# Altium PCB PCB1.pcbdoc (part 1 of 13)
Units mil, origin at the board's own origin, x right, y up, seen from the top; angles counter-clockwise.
Board outline 5895.51 x 5895.51 mil, 8 copper layers (Top Layer, L2_GND1, L3_SIG1, L4_GND2, L5_PWR, L6_SIG2, L7_GND3, Bottom Layer), stack 63.761 mil thick; 673 components, 558 nets, 2797 pads, 1861 vias.
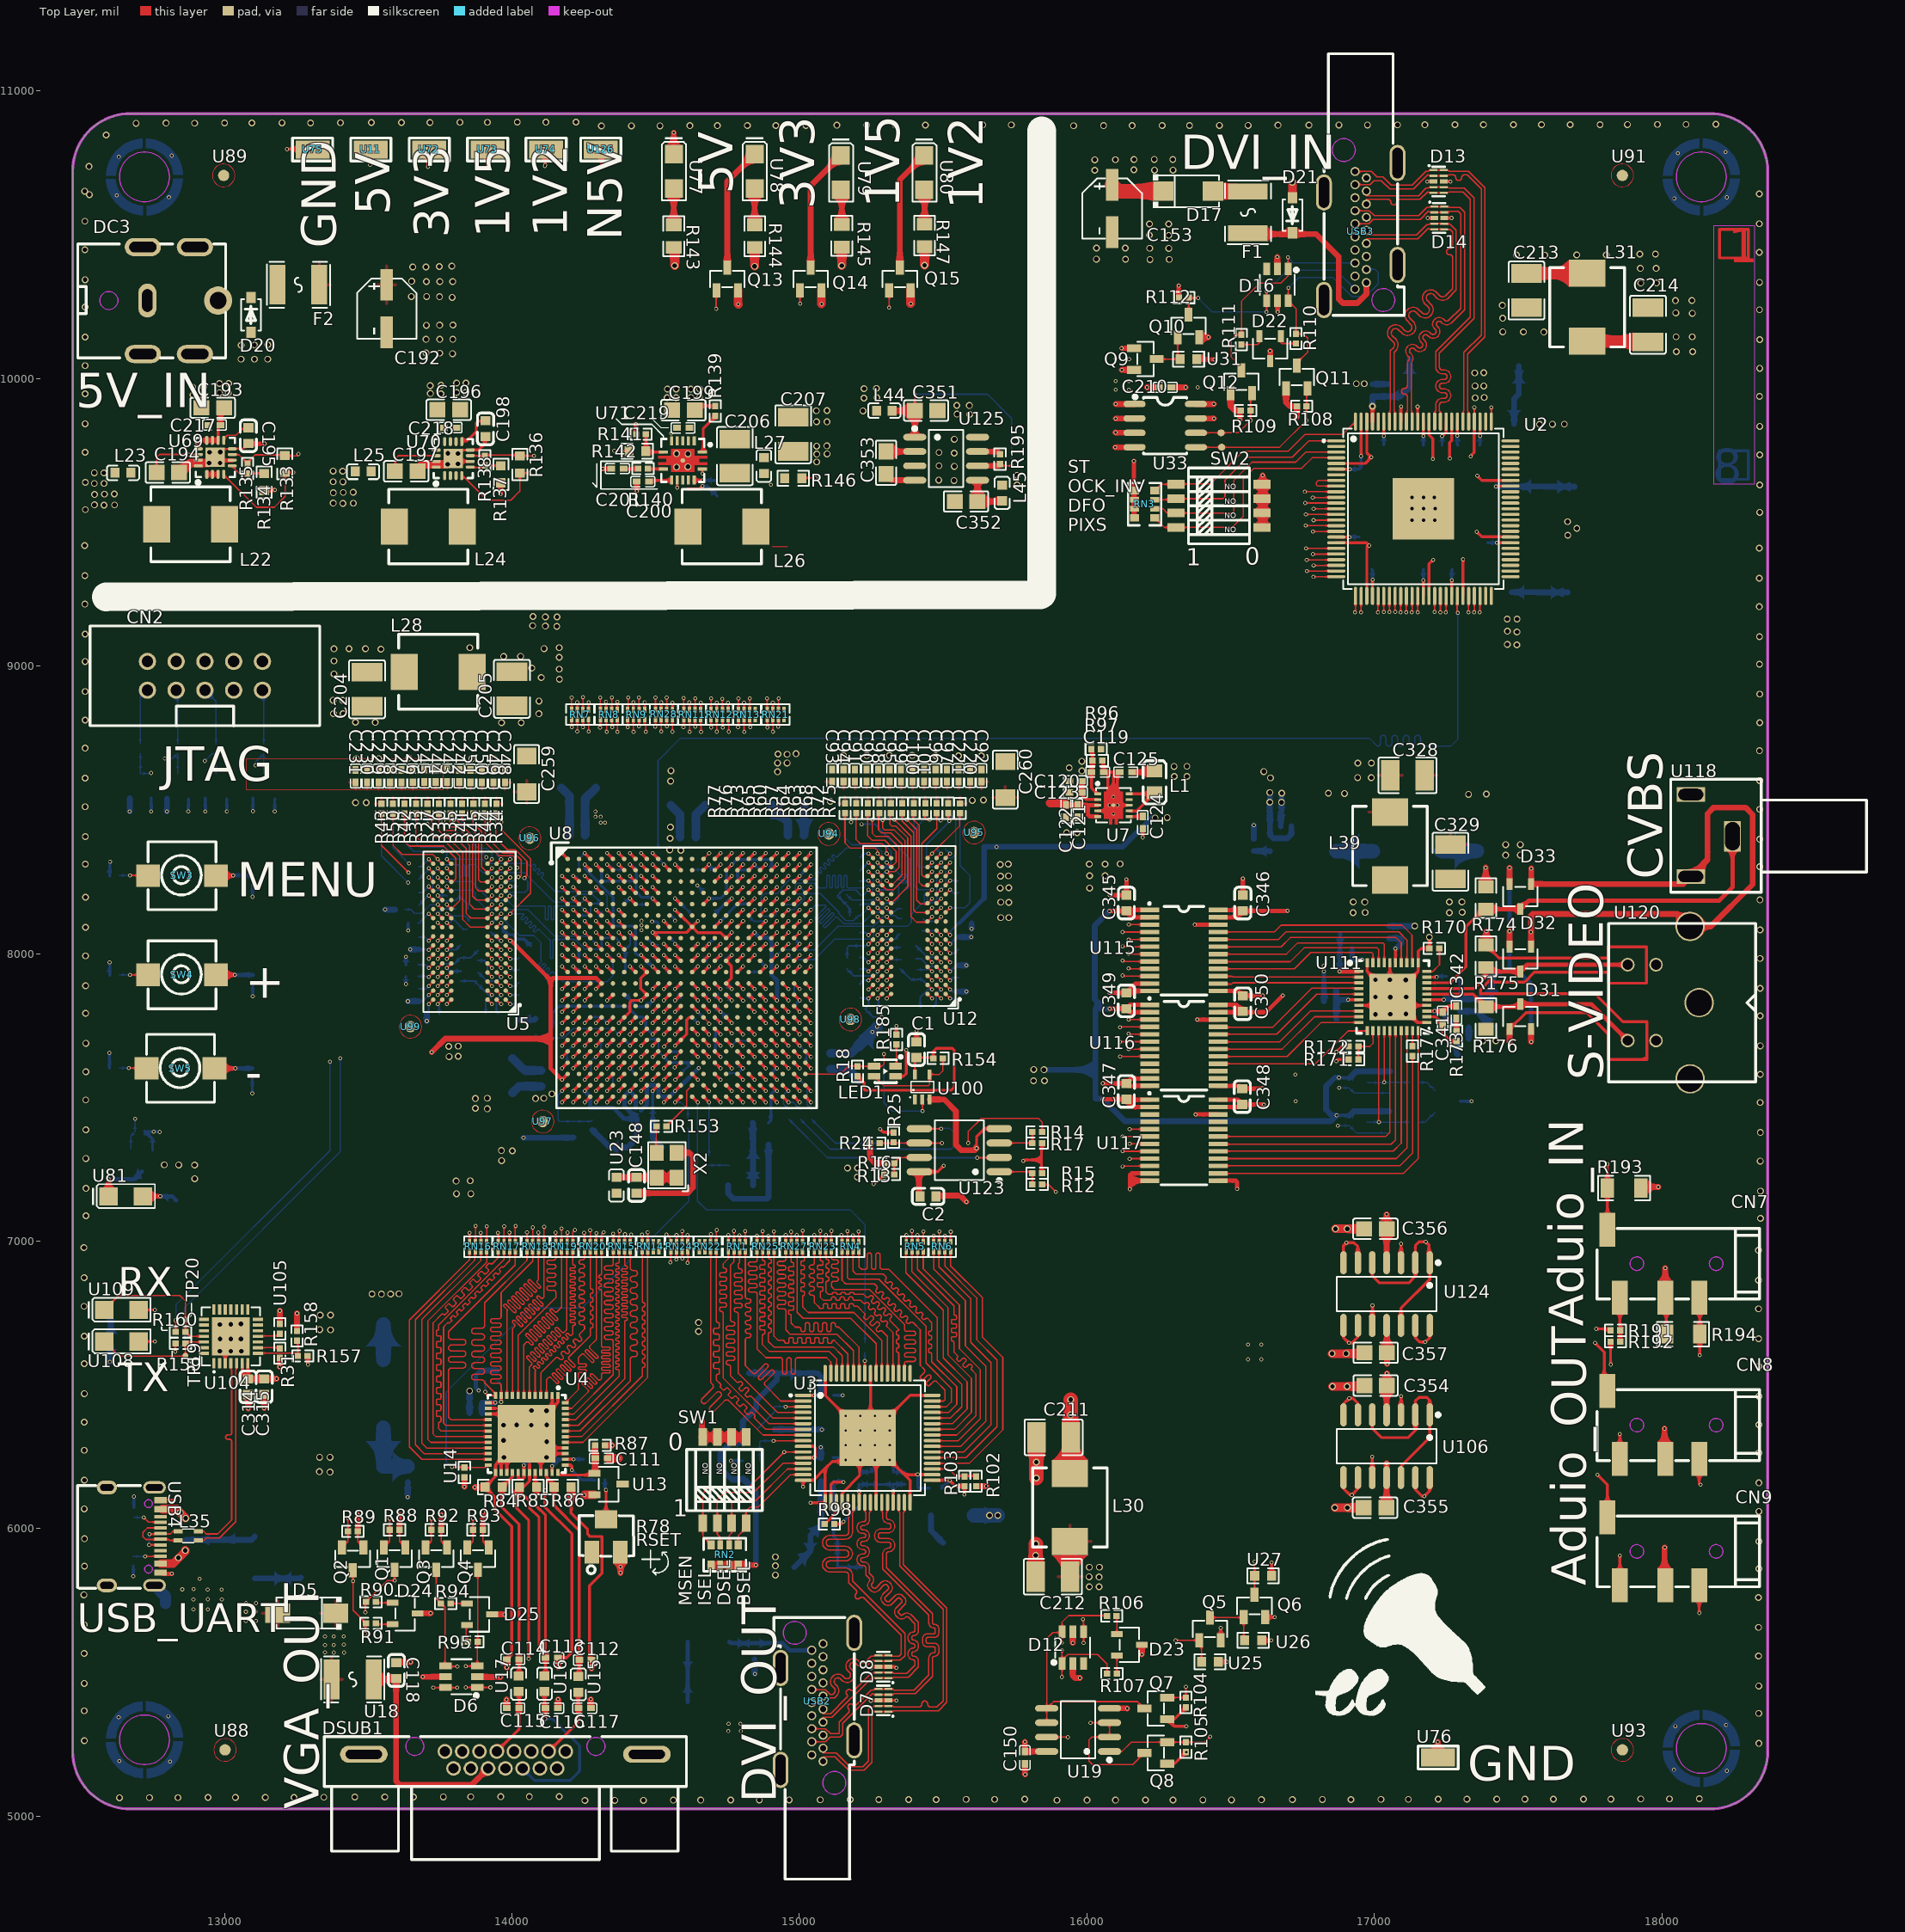
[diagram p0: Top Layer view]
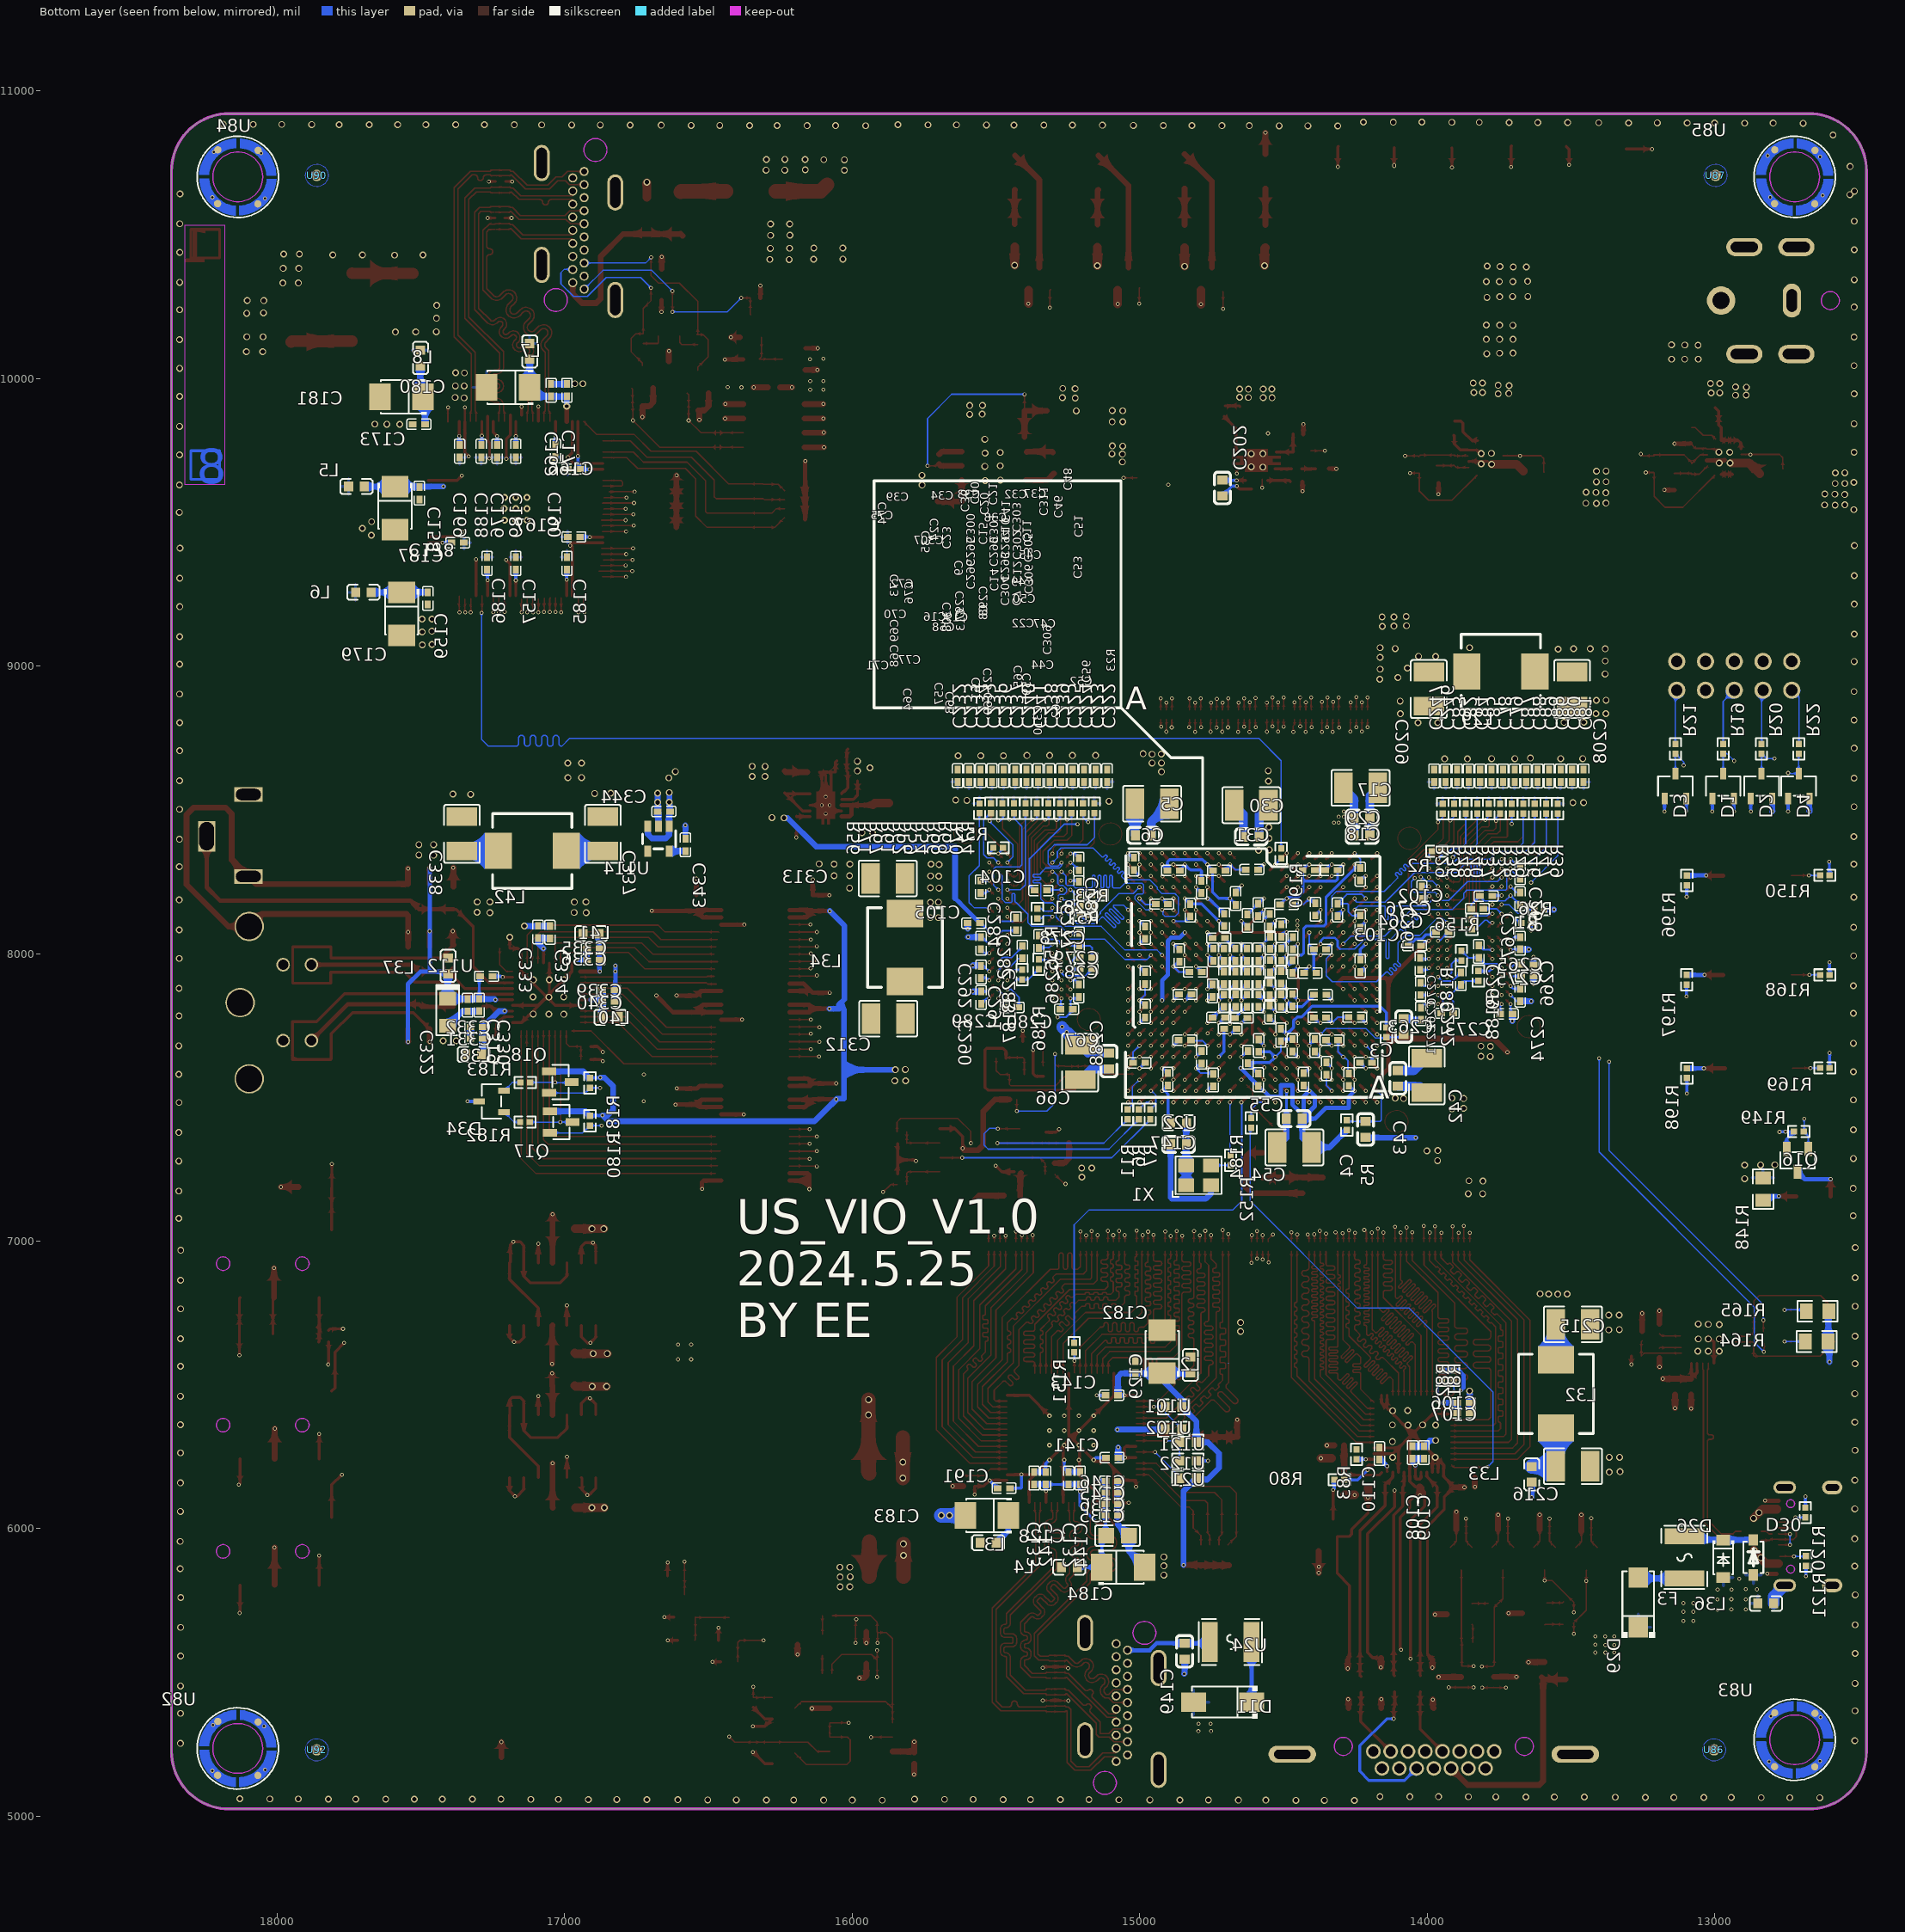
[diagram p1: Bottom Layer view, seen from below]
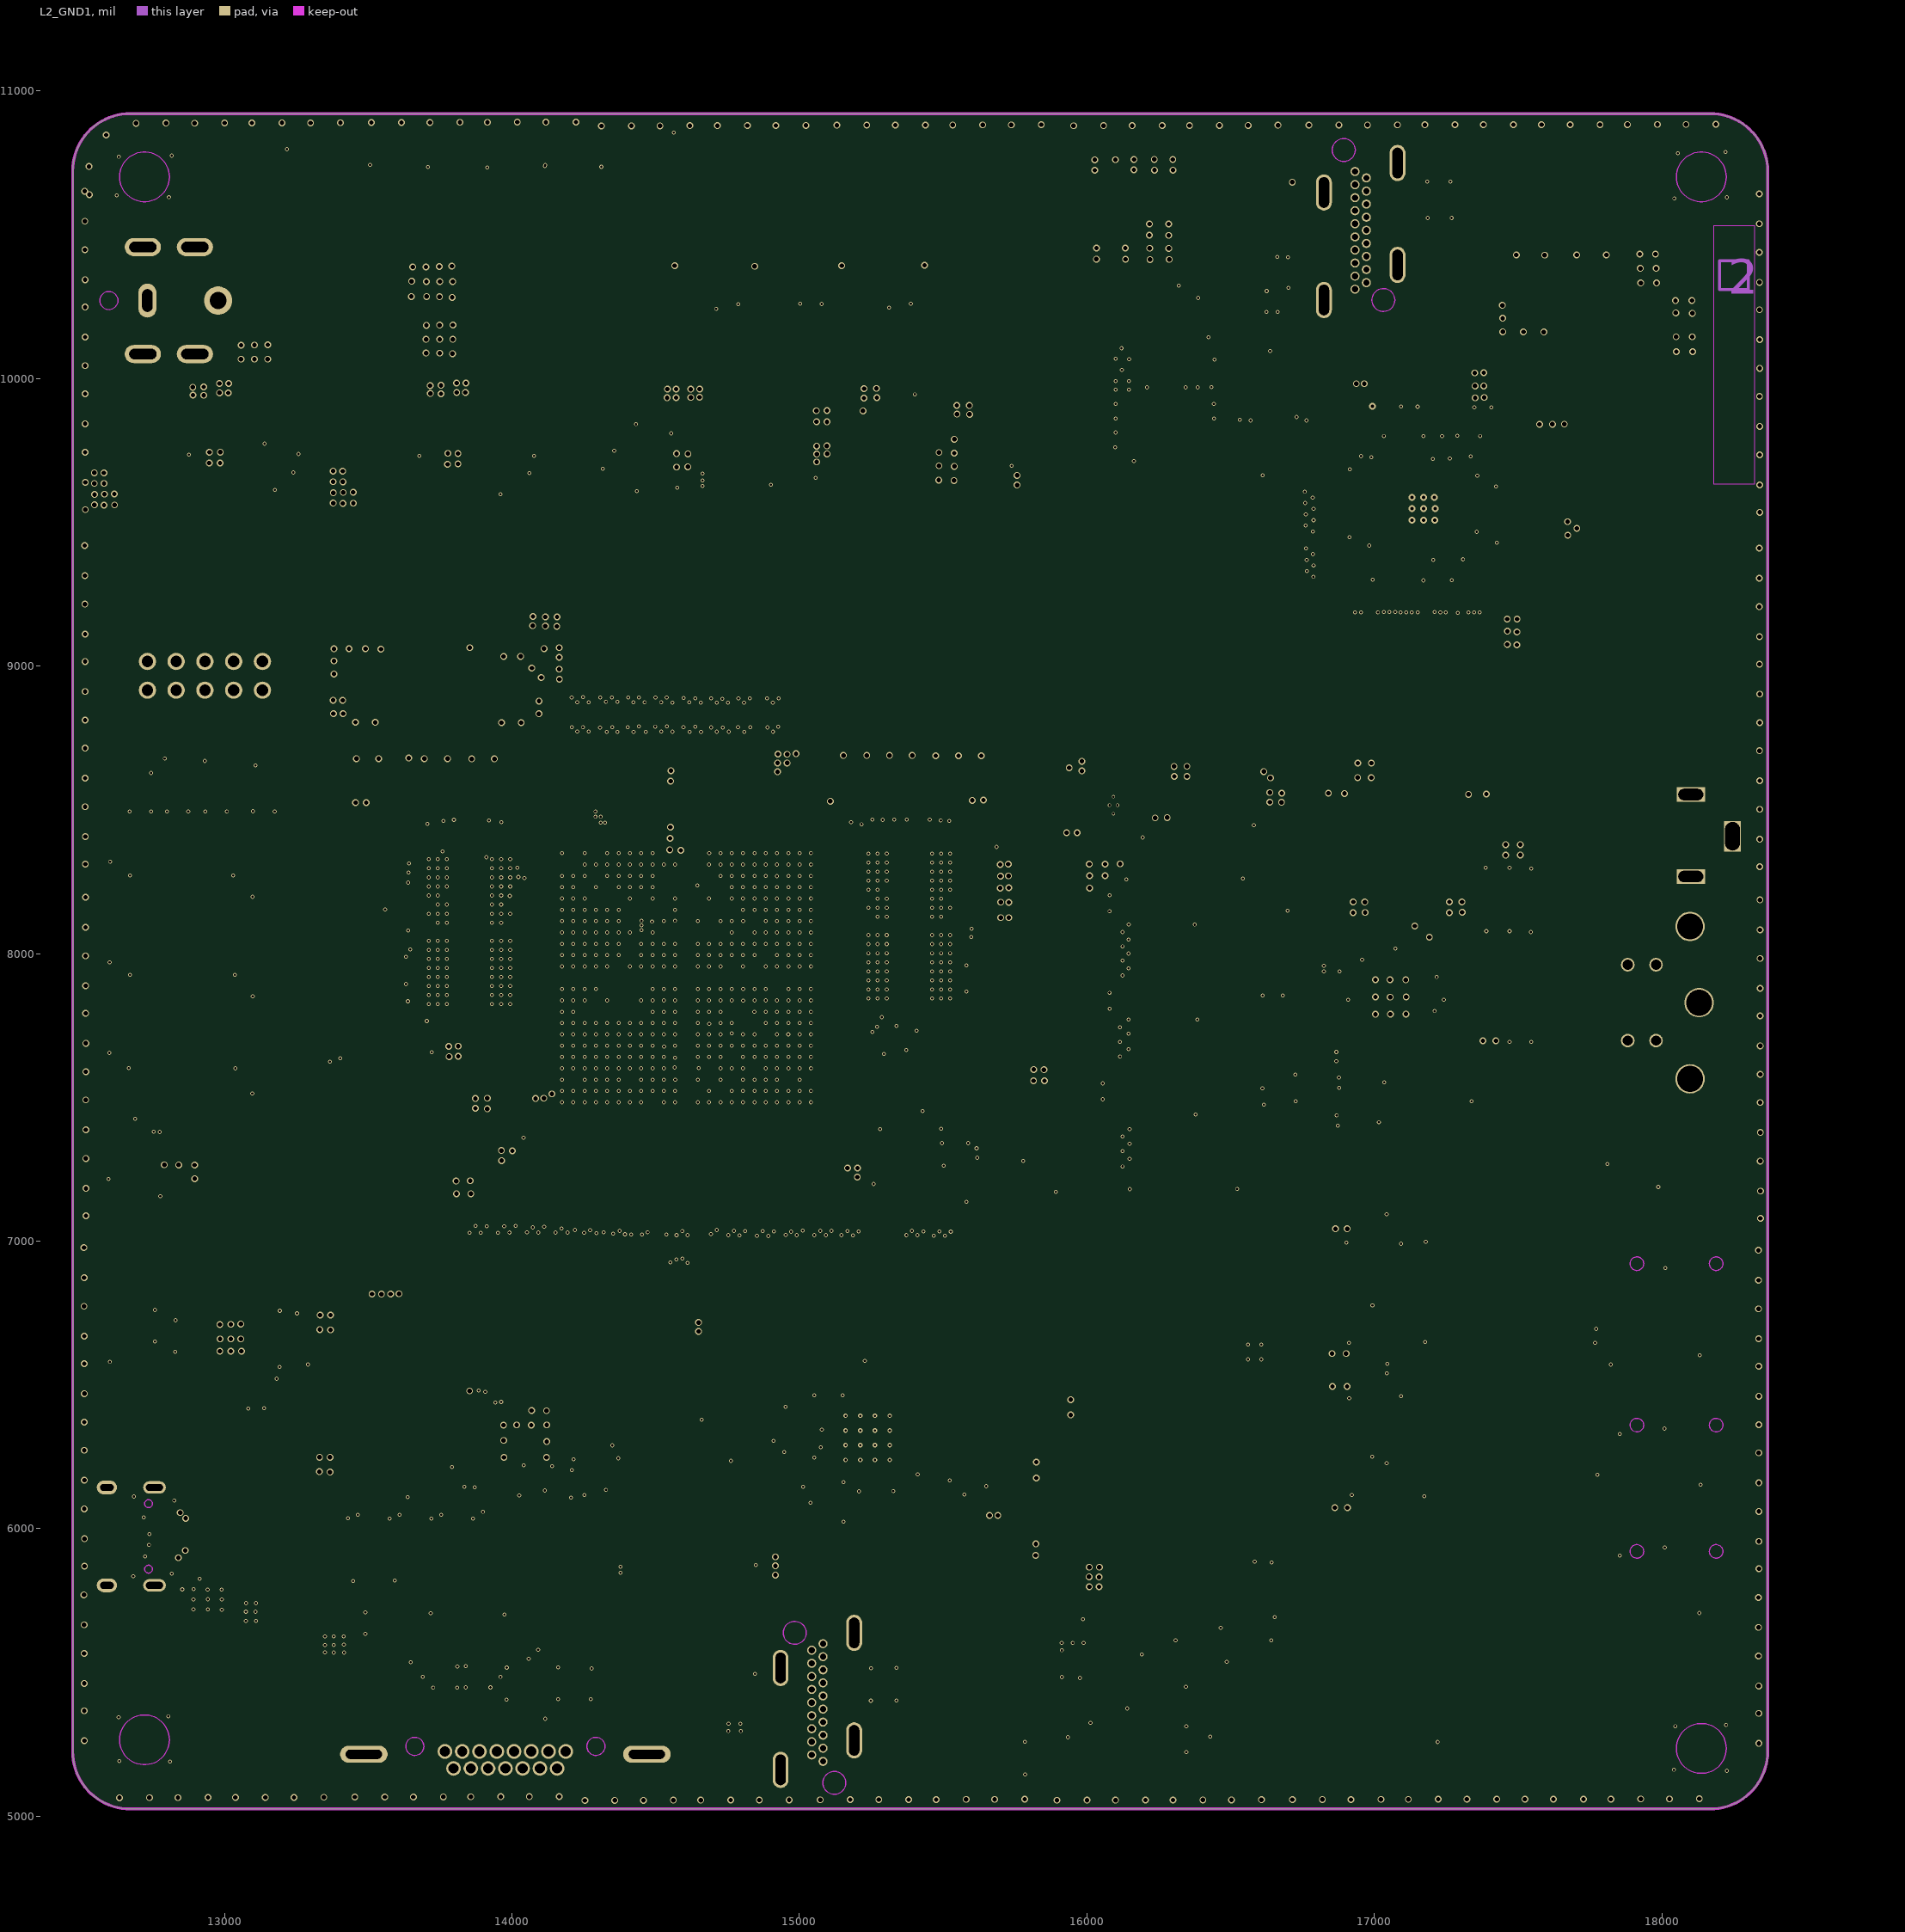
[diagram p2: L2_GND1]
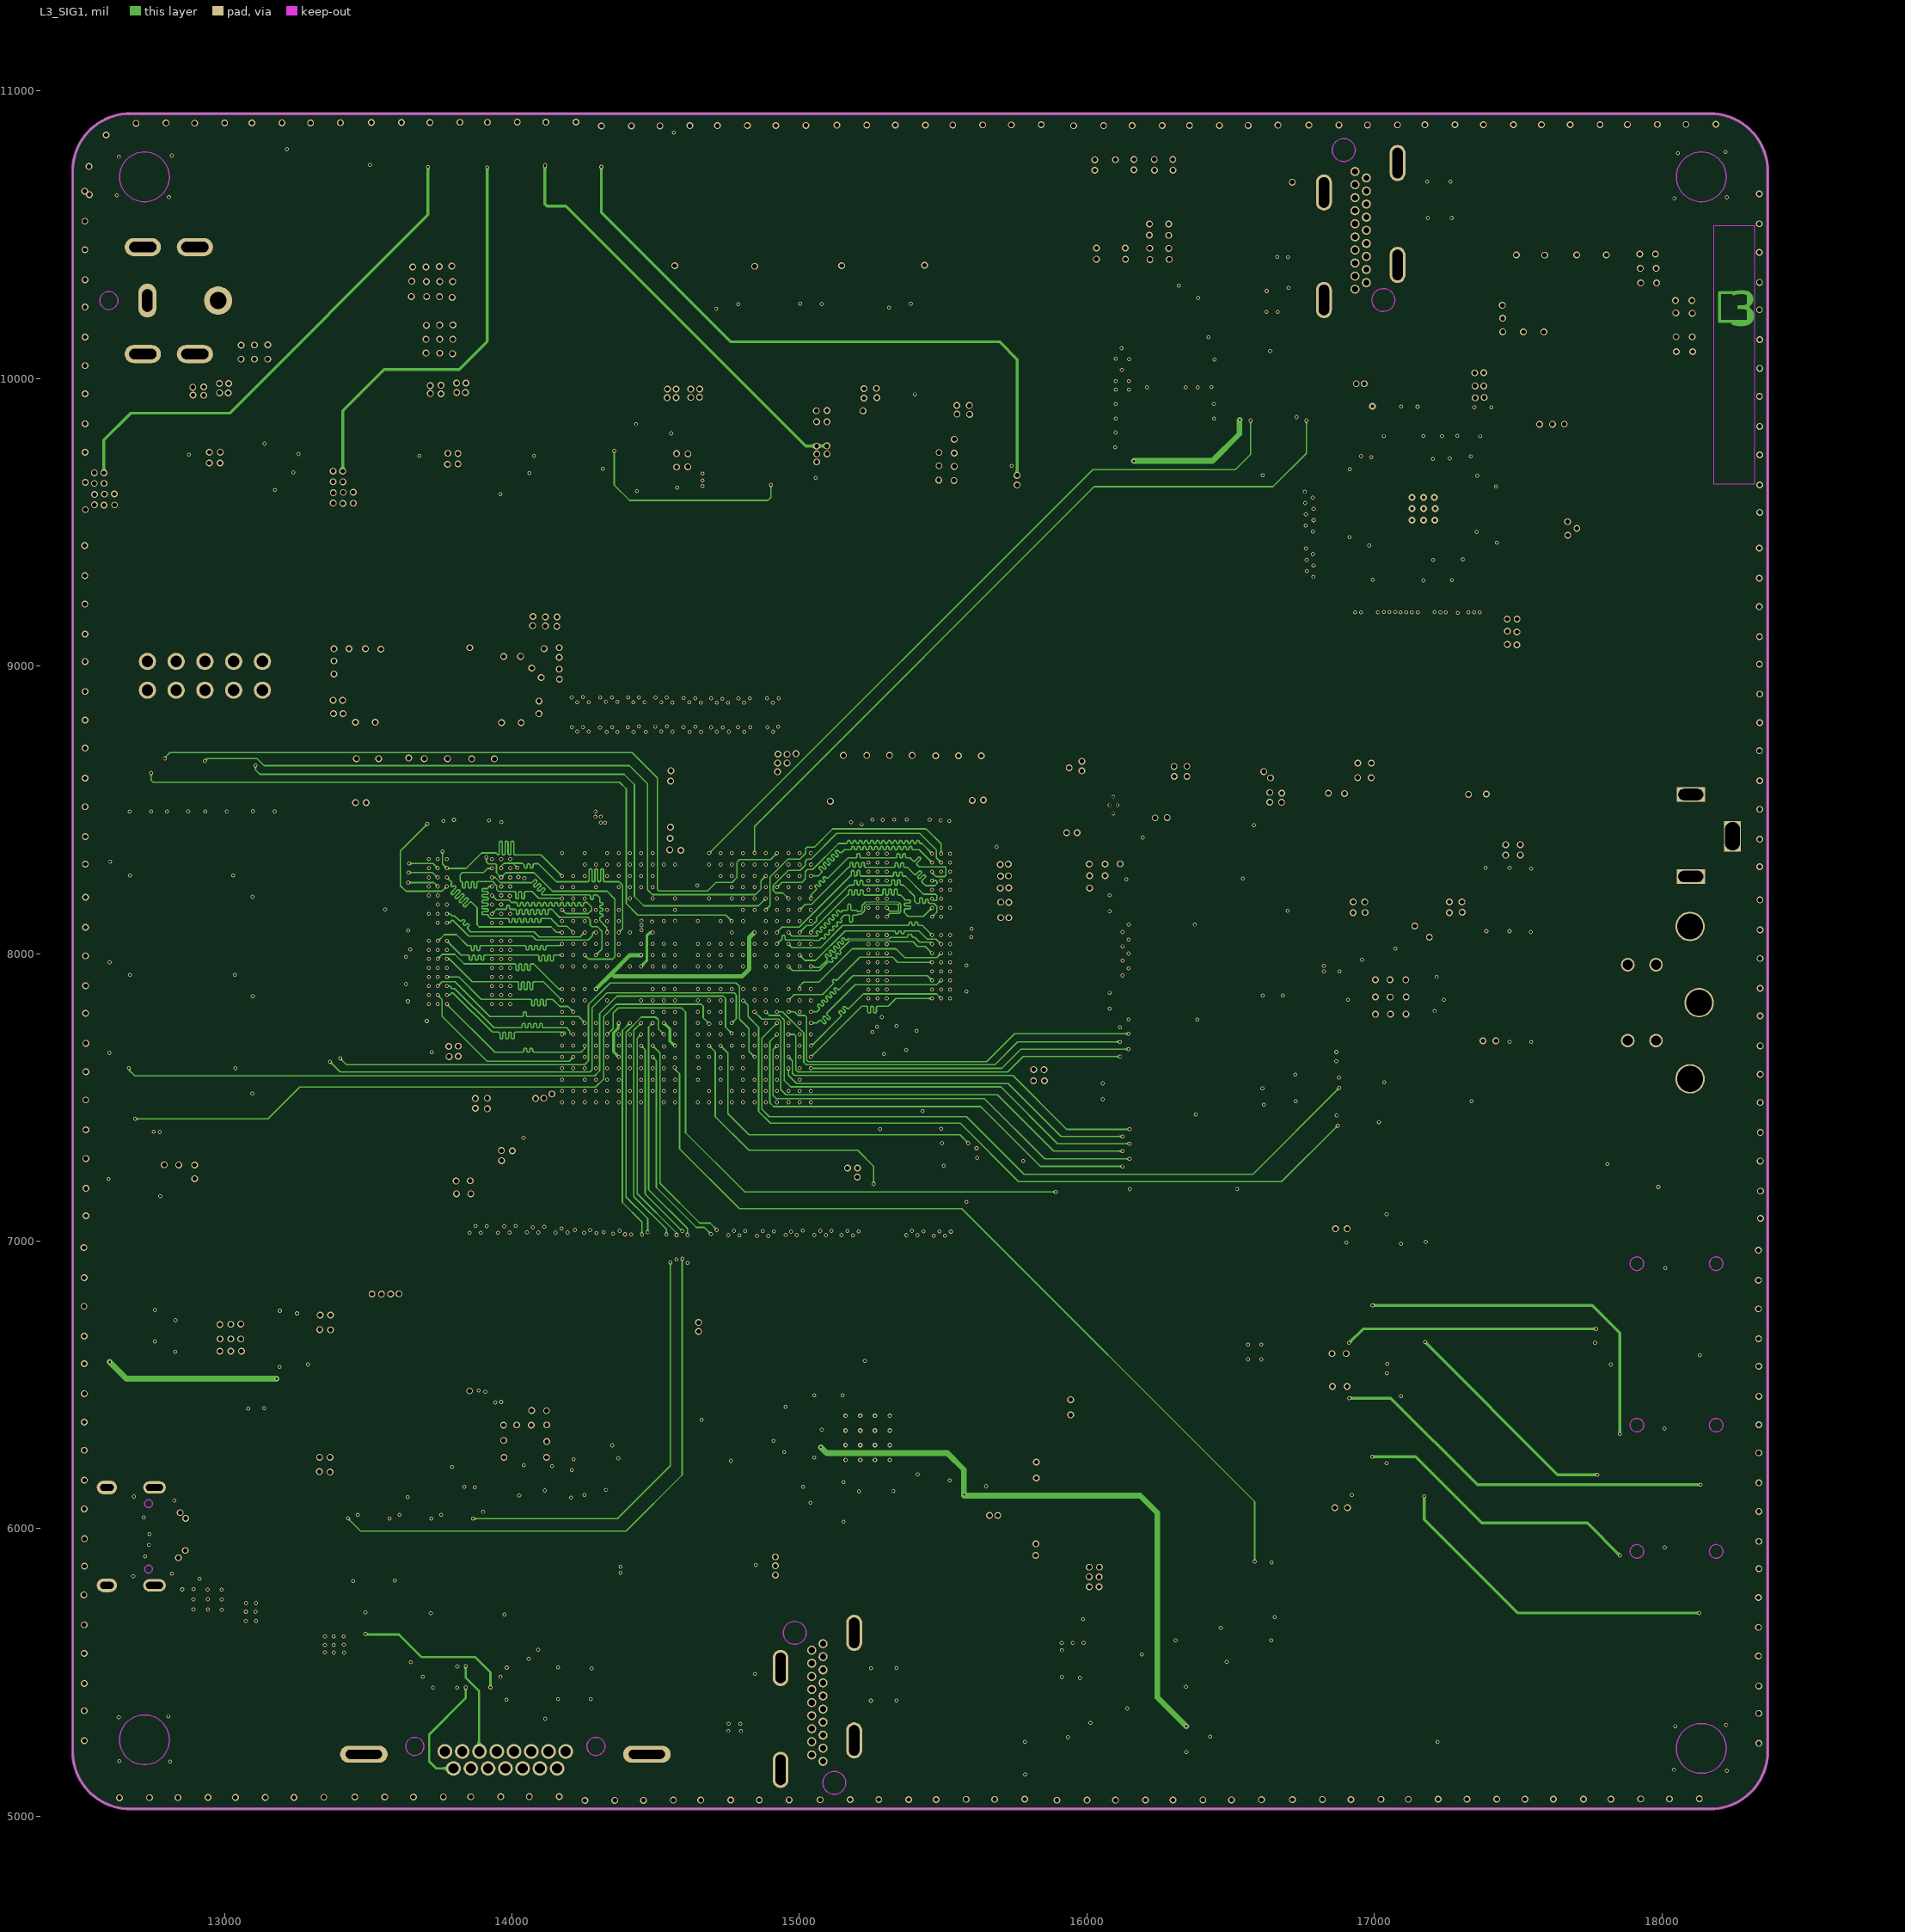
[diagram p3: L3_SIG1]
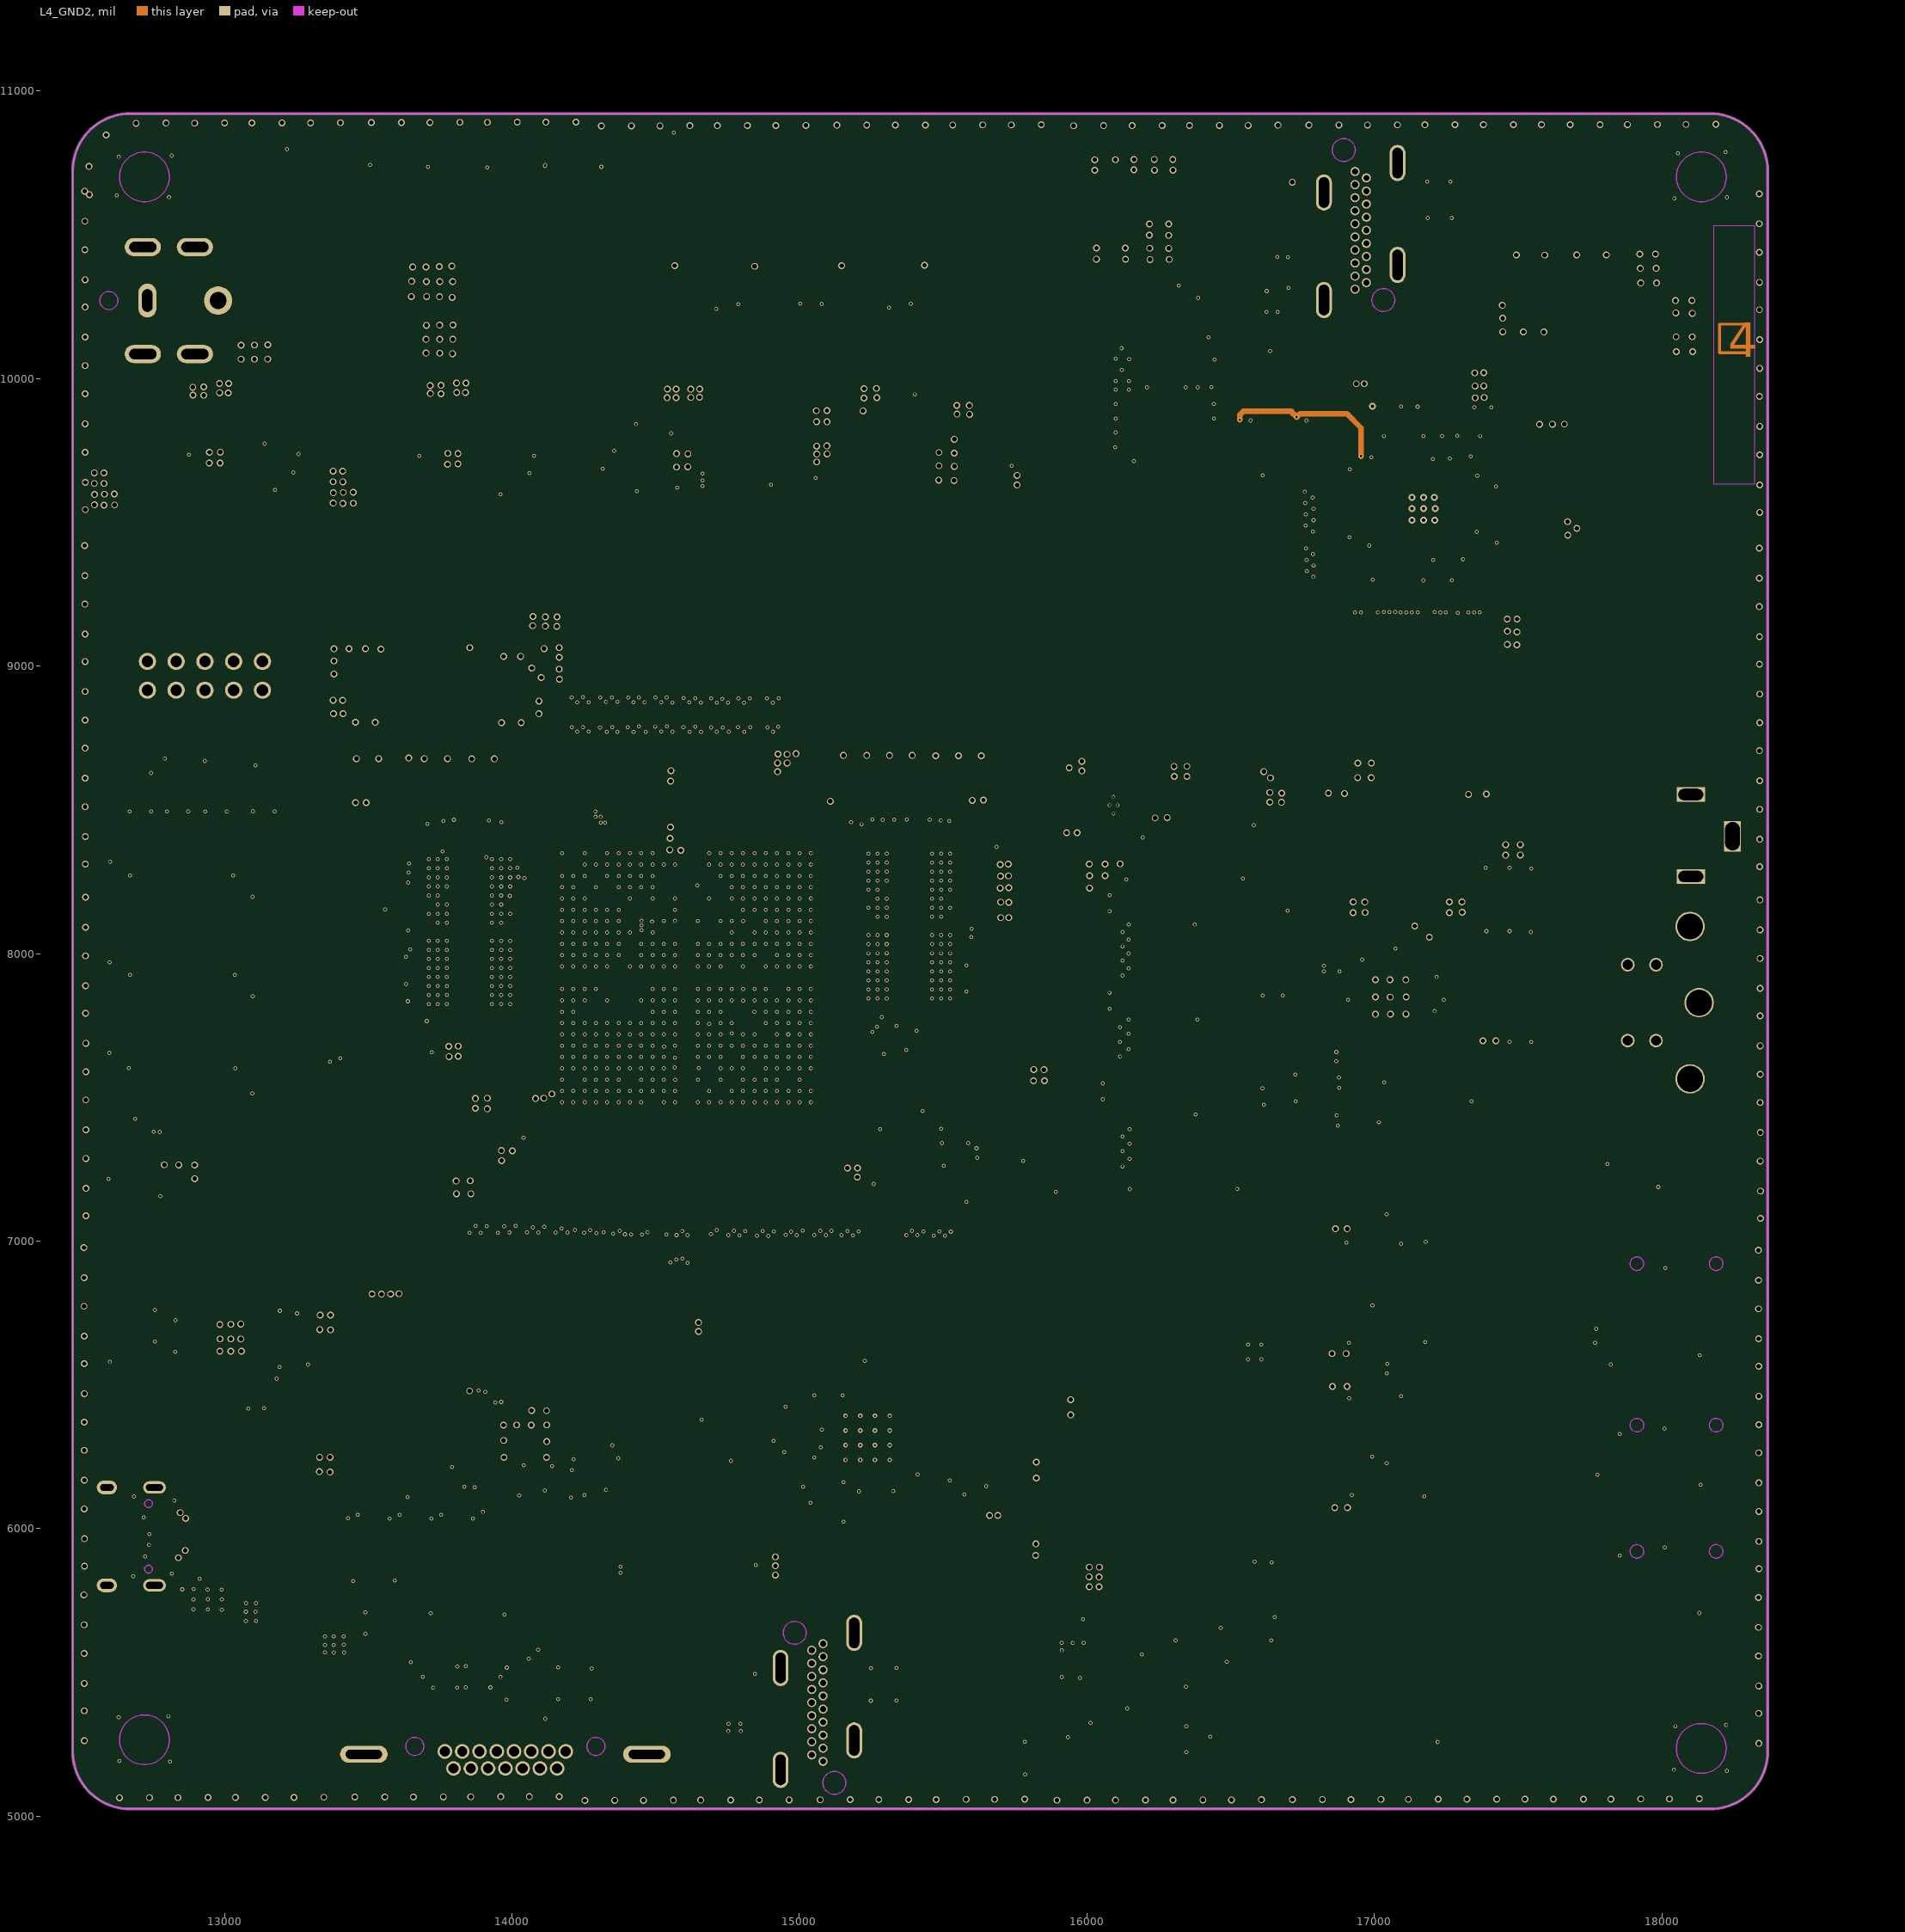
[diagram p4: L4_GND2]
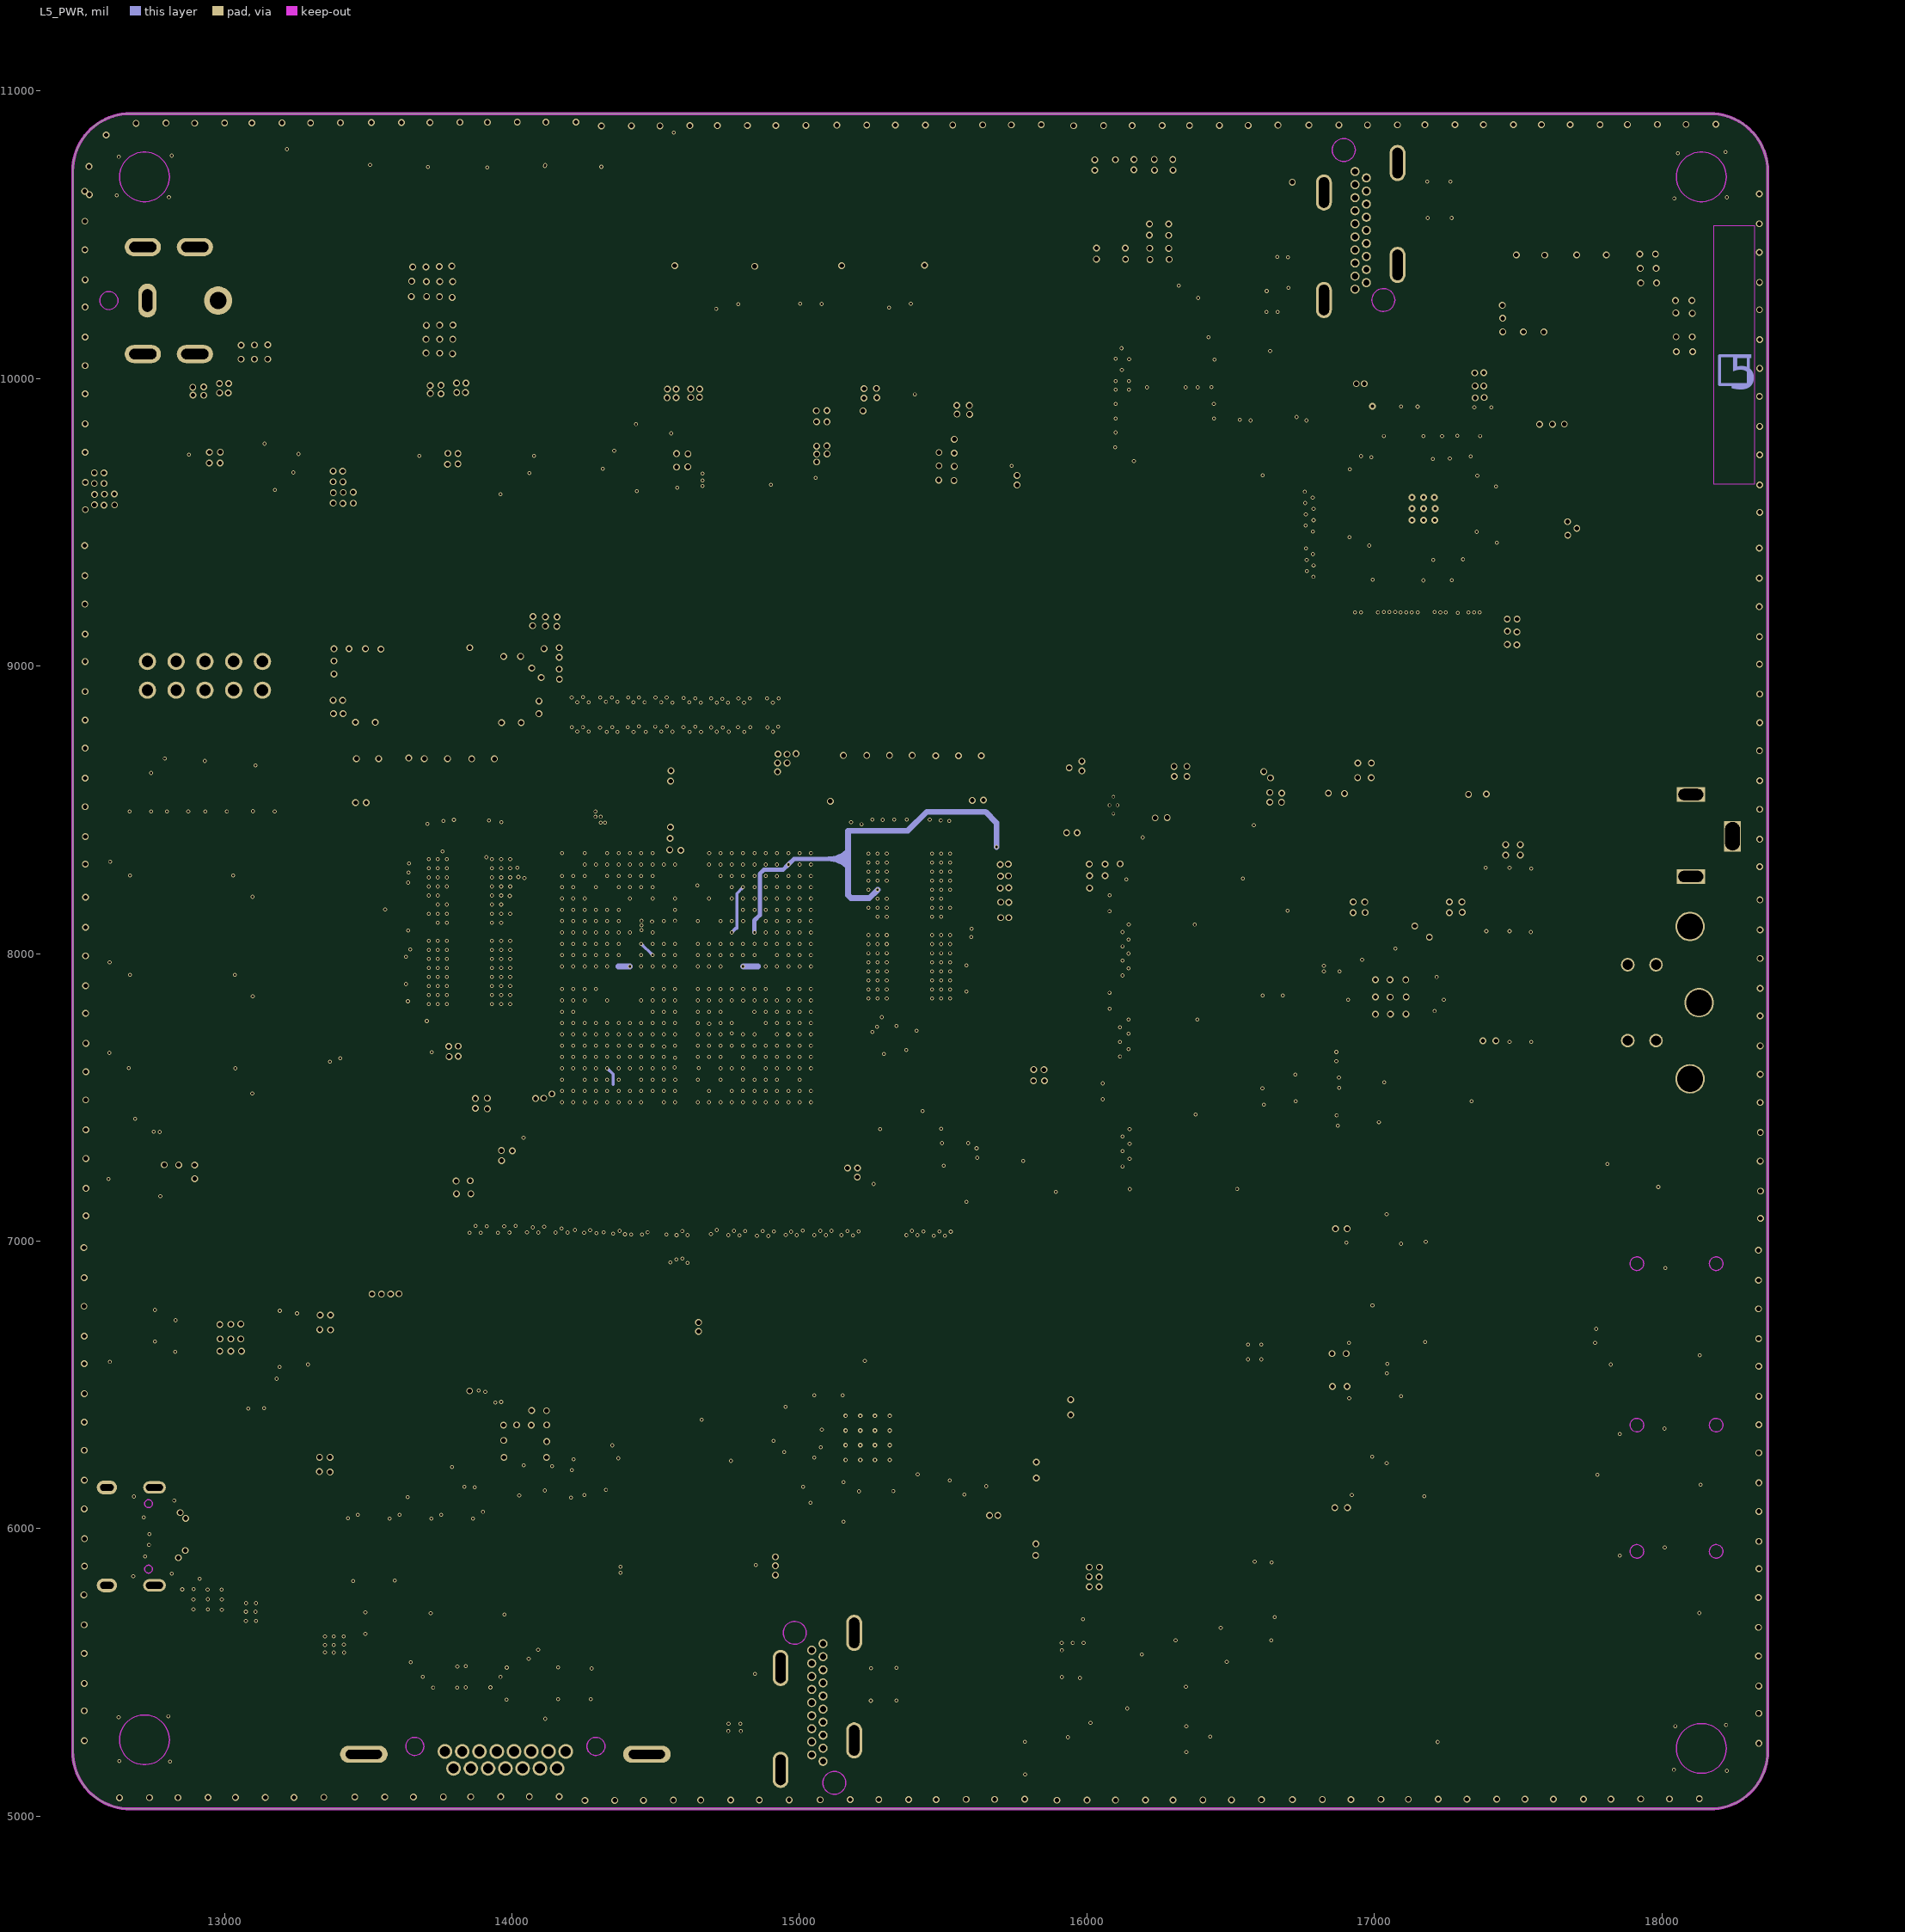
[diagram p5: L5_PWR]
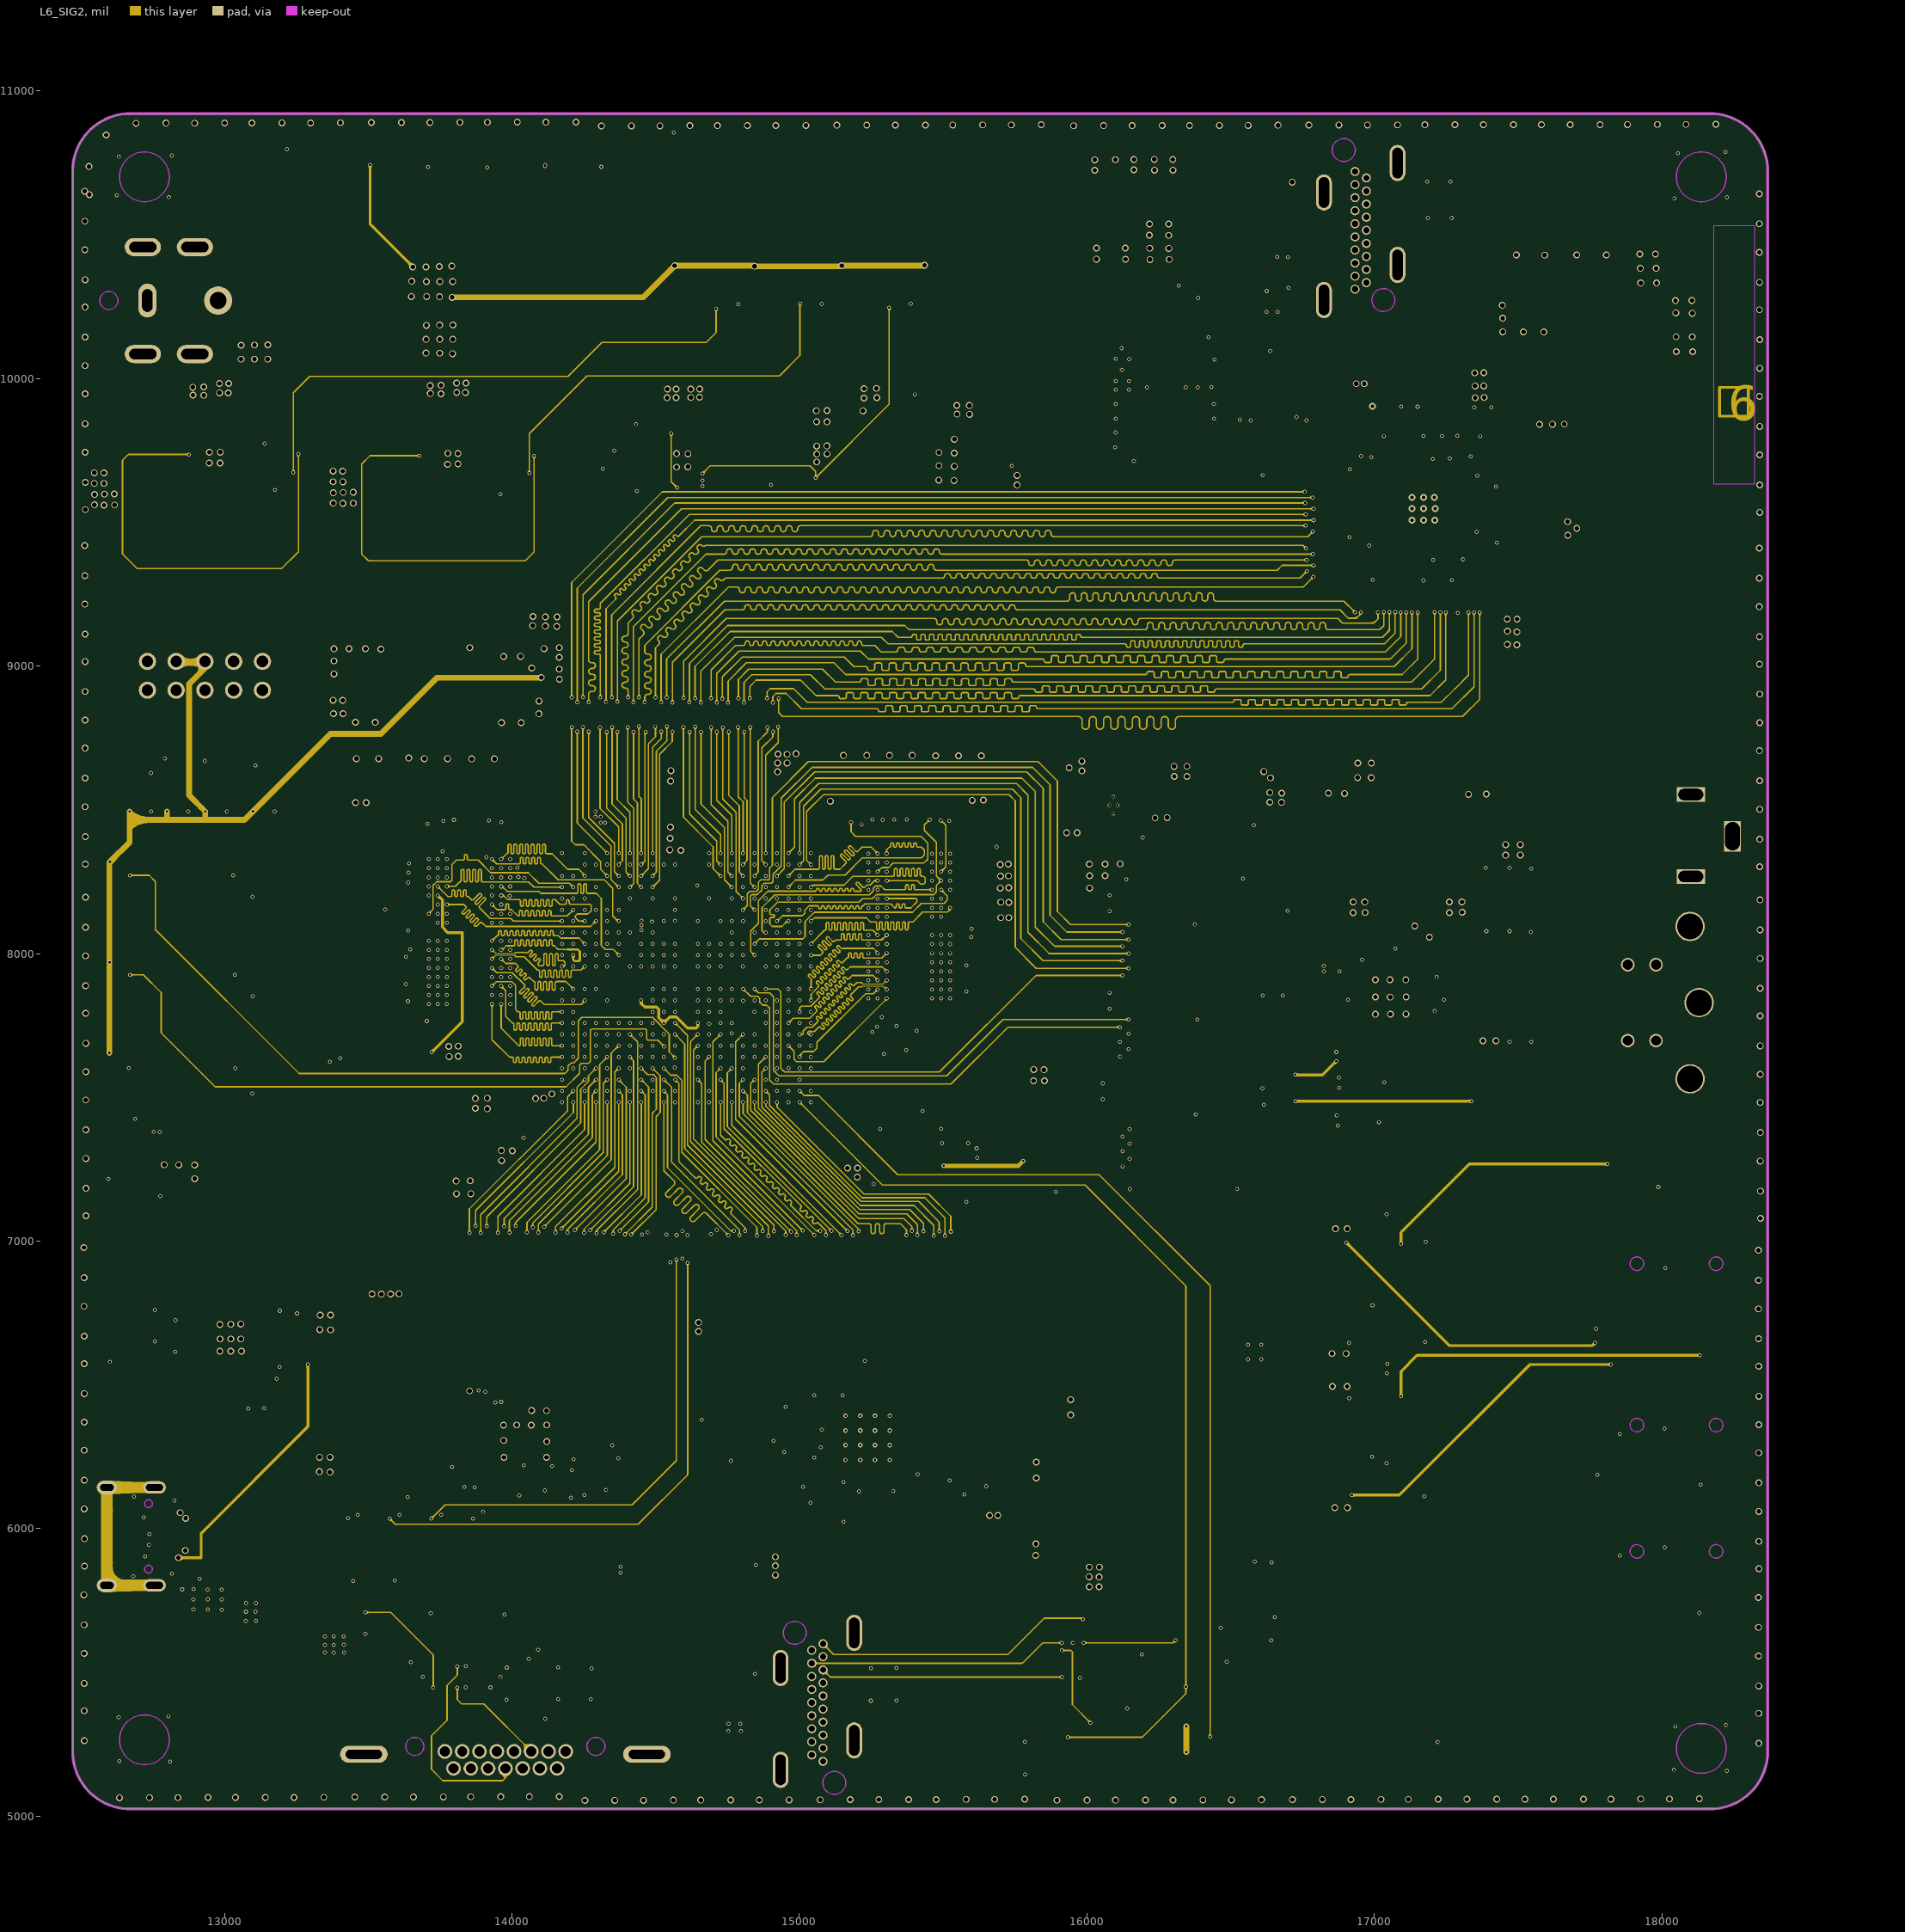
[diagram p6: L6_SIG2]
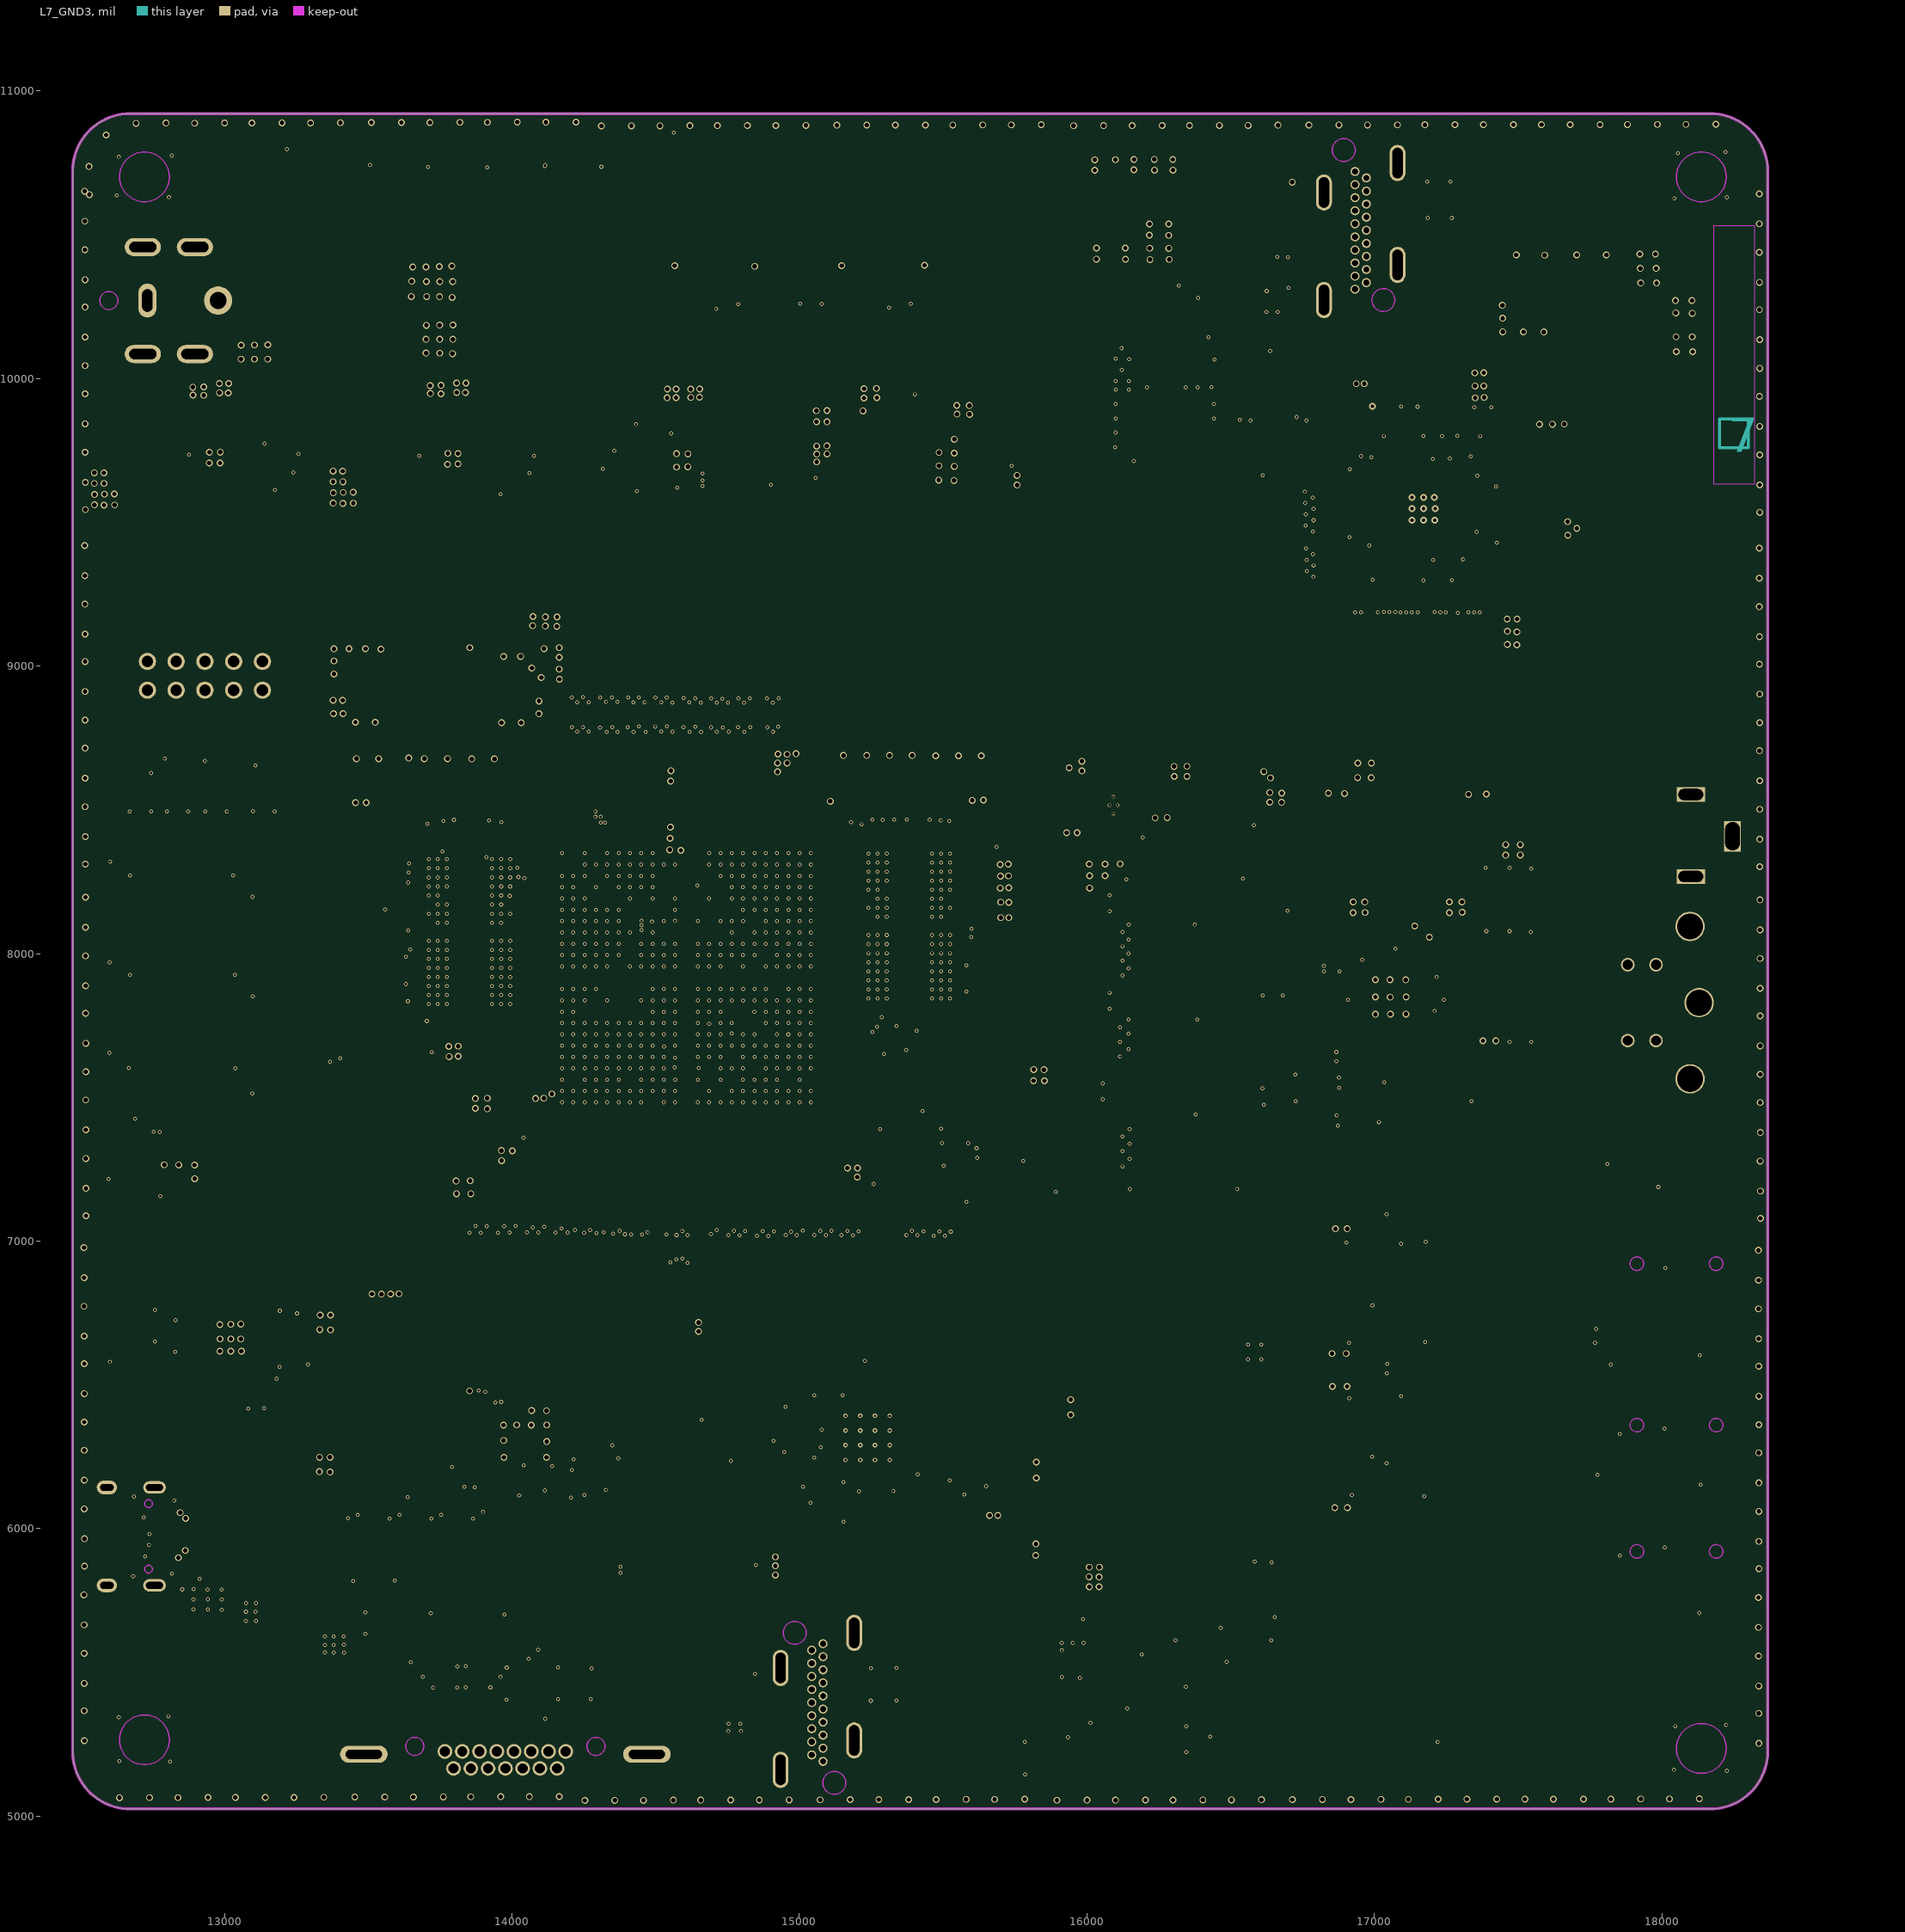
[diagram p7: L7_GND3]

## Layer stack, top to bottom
Top Layer: signal copper 1.378
Dielectric1: surface 3.008, 1080 RC67% 3.3mil, Dk 0
L2_GND1: signal copper 0.598
Dielectric2: surface 11.811, 0.3mm H/HOZ 不含铜, Dk 0
L3_SIG1: signal copper 0.598
Dielectric3: surface 7.984, 7628 RC49% 8.6mil, Dk 0
L4_GND2: signal copper 0.598
Dielectric4: surface 11.811, 0.3mm H/HOZ 不含铜, Dk 0
L5_PWR: signal copper 0.598
Dielectric5: surface 7.984, 7628 RC49% 8.6mil, Dk 0
L6_SIG2: signal copper 0.598
Dielectric6: surface 11.811, 0.3mm H/HOZ 不含铜, Dk 0
L7_GND3: signal copper 0.598
Dielectric7: surface 3.008, 1080 RC67% 3.3mil, Dk 0
Bottom Layer: signal copper 1.378

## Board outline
12672.36,10921 18167.87,10921 cw(c18167.87,10721) 18367.87,10721 18367.87,5225.49 cw(c18167.87,5225.49) 18167.87,5025.49 12672.36,5025.49 cw(c12672.36,5225.49) 12472.36,5225.49 12472.36,10721 cw(c12672.36,10721)

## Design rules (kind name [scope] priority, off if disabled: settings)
BoardOutlineClearance copperThickness1oz [All] p0: genericclearance=10 ignorepadtopadclearanceinfootprint=FALSE except(0: Arc-SplitContinuation Track-SplitContinuation SMDPad-SplitContinuation THPad-SplitContinuation Via-SplitContinuation Fill-SplitContinuation Poly-SplitContinuation Region-SplitContinuation Text-SplitContinuation)
BoardOutlineClearance copperThickness2oz [All] p0: genericclearance=10 ignorepadtopadclearanceinfootprint=FALSE except(0: Arc-SplitContinuation Track-SplitContinuation SMDPad-SplitContinuation THPad-SplitContinuation Via-SplitContinuation Fill-SplitContinuation Poly-SplitContinuation Region-SplitContinuation Text-SplitContinuation)
BoardOutlineClearance copperThicknessInner0.5oz [All] p0: genericclearance=10 ignorepadtopadclearanceinfootprint=FALSE except(0: Arc-SplitContinuation Track-SplitContinuation SMDPad-SplitContinuation THPad-SplitContinuation Via-SplitContinuation Fill-SplitContinuation Poly-SplitContinuation Region-SplitContinuation Text-SplitContinuation)
BoardOutlineClearance BGA [All] p0: genericclearance=10 ignorepadtopadclearanceinfootprint=FALSE except(0: Arc-SplitContinuation Track-SplitContinuation SMDPad-SplitContinuation THPad-SplitContinuation Via-SplitContinuation Fill-SplitContinuation Poly-SplitContinuation Region-SplitContinuation Text-SplitContinuation)
BoardOutlineClearance Plane_innerPlane [All] p0: genericclearance=10 ignorepadtopadclearanceinfootprint=FALSE except(0: Arc-SplitContinuation Track-SplitContinuation SMDPad-SplitContinuation THPad-SplitContinuation Via-SplitContinuation Fill-SplitContinuation Poly-SplitContinuation Region-SplitContinuation Text-SplitContinuation)
BoardOutlineClearance Copper_copperRegion1 [All] p0: genericclearance=10 ignorepadtopadclearanceinfootprint=FALSE except(0: Arc-SplitContinuation Track-SplitContinuation SMDPad-SplitContinuation THPad-SplitContinuation Via-SplitContinuation Fill-SplitContinuation Poly-SplitContinuation Region-SplitContinuation Text-SplitContinuation)
BoardOutlineClearance Copper_copperRegion2 [All] p0: genericclearance=10 ignorepadtopadclearanceinfootprint=FALSE except(0: Arc-SplitContinuation Track-SplitContinuation SMDPad-SplitContinuation THPad-SplitContinuation Via-SplitContinuation Fill-SplitContinuation Poly-SplitContinuation Region-SplitContinuation Text-SplitContinuation)
BoardOutlineClearance Copper_copperRegion3 [All] p0: genericclearance=10 ignorepadtopadclearanceinfootprint=FALSE except(0: Arc-SplitContinuation Track-SplitContinuation SMDPad-SplitContinuation THPad-SplitContinuation Via-SplitContinuation Fill-SplitContinuation Poly-SplitContinuation Region-SplitContinuation Text-SplitContinuation)
BoardOutlineClearance otherClearance [All] p0: genericclearance=10 ignorepadtopadclearanceinfootprint=FALSE except(0: Arc-SplitContinuation Track-SplitContinuation SMDPad-SplitContinuation THPad-SplitContinuation Via-SplitContinuation Fill-SplitContinuation Poly-SplitContinuation Region-SplitContinuation Text-SplitContinuation)
Clearance copperThickness1oz [All] p1: gap=7 ignorepadtopadclearanceinfootprint=FALSE
Clearance copperThickness2oz [All] p1: gap=7 ignorepadtopadclearanceinfootprint=FALSE
Clearance copperThicknessInner0.5oz [All] p1: gap=7 ignorepadtopadclearanceinfootprint=FALSE
Clearance BGA [All] p1: gap=7 ignorepadtopadclearanceinfootprint=FALSE
Clearance Plane_innerPlane [All] p1: gap=7 ignorepadtopadclearanceinfootprint=FALSE
Clearance Copper_copperRegion1 [All] p1: gap=7 ignorepadtopadclearanceinfootprint=FALSE
Clearance Copper_copperRegion2 [All] p1: gap=7 ignorepadtopadclearanceinfootprint=FALSE
Clearance Copper_copperRegion3 [All] p1: gap=7 ignorepadtopadclearanceinfootprint=FALSE
Clearance otherClearance [All] p1: gap=7 ignorepadtopadclearanceinfootprint=FALSE
DiffPairsRouting differentialPair [All] p1: maxuncoupledlength=10 minlimit=6 maxlimit=Infinity mostfreqgap=9 toplayer_minwidth=4 toplayer_prefwidth=10 toplayer_maxwidth=100 bottomlayer_minwidth=4 bottomlayer_prefwidth=10 bottomlayer_maxwidth=100 midlayer1_minwidth=4 midlayer1_prefwidth=10 midlayer1_maxwidth=100 midlayer2_minwidth=4 midlayer2_prefwidth=10 midlayer2_maxwidth=100 midlayer3_minwidth=4 midlayer3_prefwidth=10 midlayer3_maxwidth=100 midlayer4_minwidth=4 midlayer4_prefwidth=10 midlayer4_maxwidth=100 midlayer5_minwidth=4 midlayer5_prefwidth=10 midlayer5_maxwidth=100 midlayer6_minwidth=4 midlayer6_prefwidth=10 midlayer6_maxwidth=100
DiffPairsRouting 100R_L1/8 [All] p1: maxuncoupledlength=10 minlimit=3.5 maxlimit=Infinity mostfreqgap=9 toplayer_minwidth=3.5 toplayer_prefwidth=4 toplayer_maxwidth=10 bottomlayer_minwidth=3.5 bottomlayer_prefwidth=4 bottomlayer_maxwidth=10 midlayer1_minwidth=3.5 midlayer1_prefwidth=4 midlayer1_maxwidth=10 midlayer2_minwidth=3.5 midlayer2_prefwidth=4 midlayer2_maxwidth=10 midlayer3_minwidth=3.5 midlayer3_prefwidth=4 midlayer3_maxwidth=10 midlayer4_minwidth=3.5 midlayer4_prefwidth=4 midlayer4_maxwidth=10 midlayer5_minwidth=3.5 midlayer5_prefwidth=4 midlayer5_maxwidth=10 midlayer6_minwidth=3.5 midlayer6_prefwidth=4 midlayer6_maxwidth=10
DiffPairsRouting 100R_L3/6 [All] p1: maxuncoupledlength=10 minlimit=3.5 maxlimit=Infinity mostfreqgap=9 toplayer_minwidth=3.5 toplayer_prefwidth=6.2 toplayer_maxwidth=8 bottomlayer_minwidth=3.5 bottomlayer_prefwidth=6.2 bottomlayer_maxwidth=8 midlayer1_minwidth=3.5 midlayer1_prefwidth=6.2 midlayer1_maxwidth=8 midlayer2_minwidth=3.5 midlayer2_prefwidth=6.2 midlayer2_maxwidth=8 midlayer3_minwidth=3.5 midlayer3_prefwidth=6.2 midlayer3_maxwidth=8 midlayer4_minwidth=3.5 midlayer4_prefwidth=6.2 midlayer4_maxwidth=8 midlayer5_minwidth=3.5 midlayer5_prefwidth=6.2 midlayer5_maxwidth=8 midlayer6_minwidth=3.5 midlayer6_prefwidth=6.2 midlayer6_maxwidth=8
DiffPairsRouting 90R_L1/L8 [All] p1: maxuncoupledlength=10 minlimit=6 maxlimit=Infinity mostfreqgap=9 toplayer_minwidth=4 toplayer_prefwidth=5.1 toplayer_maxwidth=8 bottomlayer_minwidth=4 bottomlayer_prefwidth=5.1 bottomlayer_maxwidth=8 midlayer1_minwidth=4 midlayer1_prefwidth=5.1 midlayer1_maxwidth=8 midlayer2_minwidth=4 midlayer2_prefwidth=5.1 midlayer2_maxwidth=8 midlayer3_minwidth=4 midlayer3_prefwidth=5.1 midlayer3_maxwidth=8 midlayer4_minwidth=4 midlayer4_prefwidth=5.1 midlayer4_maxwidth=8 midlayer5_minwidth=4 midlayer5_prefwidth=5.1 midlayer5_maxwidth=8 midlayer6_minwidth=4 midlayer6_prefwidth=5.1 midlayer6_maxwidth=8
PasteMaskExpansion pasteMaskExpansion [All] p1: expansion=0
PlaneConnect innerPlane [All] p1: planeconnectstyle=Relief reliefexpansion=20 reliefentries=4 reliefconductorwidth=10 reliefairgap=10
PolygonConnect copperRegion1 [All] p1: connectstyle=Direct reliefentries=4 reliefconductorwidth=10 polygonreliefangle="90 Angle" airgapwidth=10
PolygonConnect copperRegion2 [All] p1: connectstyle=Direct reliefentries=4 reliefconductorwidth=10 polygonreliefangle="90 Angle" airgapwidth=10
PolygonConnect copperRegion3 [All] p1: connectstyle=Direct reliefentries=4 reliefconductorwidth=10 polygonreliefangle="90 Angle" airgapwidth=10
RoutingVias viaSize [All] p1: viastyle="Through Hole" holewidth=11.8 minholewidth=7.9 maxholewidth=248 width=11.8 minwidth=7.9 maxwidth=248
SolderMaskExpansion solderMaskExpansion [All] p1: useseparateexpansions=TRUE expansion=2 expansionbottom=2
Width copperThickness1oz [All] p1: maxlimit=100 minlimit=4 preferedwidth=10
Width copperThickness2oz [All] p1: maxlimit=100 minlimit=8 preferedwidth=10
Width copperThickness0.5oz [All] p1: maxlimit=100 minlimit=4 preferedwidth=10
Width 50R_L1/L8 [All] p1: maxlimit=50 minlimit=4 preferedwidth=5
Width 50R_L3/6 [All] p1: maxlimit=50 minlimit=4 preferedwidth=8
Width 45R_L1/L8 [All] p1: maxlimit=50 minlimit=4 preferedwidth=6
Width Power [All] p1: maxlimit=100 minlimit=5 preferedwidth=10

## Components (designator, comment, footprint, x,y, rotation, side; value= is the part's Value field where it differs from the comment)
C1 "" C0603 15407.36,7666 r270 top
C2 "" C0603 15447.36,7156 r180 top
C3 "" C0603 14082.36,7746 r270 bottom
C4 "" C0603 14214.71,7388.97 r90 bottom
C5 "" C1210 14957.36,8521 r0 bottom
C6 "" C0603 14987.36,8411 r0 bottom
C7 "" C0402 14508.65,7836.89 r270 bottom
C8 "" C0402 14627.36,7836 r90 bottom
C9 "" C0402 14707.36,7996 r90 bottom
C10 "" C0402 14546.62,8037.47 r270 bottom
C11 "" C0402 14467.36,8036 r270 bottom
C12 "" C0402 14508.38,7917.45 r270 bottom
C13 "" C0402 14707.36,7836 r90 bottom
C14 "" C0402 14587.36,7836 r270 bottom
C15 "" C0402 14627.36,7996 r90 bottom
C16 "" C0402 14725.36,7778 r180 bottom
C17 "" C1210 14232.36,8576 r0 bottom
C18 "" C0603 14227.36,8411 r0 bottom
C19 "" C0402 14647.36,7776 r180 bottom
C20 "" C0402 14625.36,8115 r270 bottom
C21 "" C0402 14588.36,8152 r270 bottom
C22 "" C0402 14373.36,7778 r0 bottom
C23 "" C0402 14744.36,7996 r270 bottom
C24 "" C0402 14785.36,8232 r270 bottom
C25 "" C0402 14586.36,7680 r90 bottom
C29 "" C0603 14227.36,8471 r0 bottom
C30 "" C1210 14612.36,8516 r180 bottom
C31 "" C0603 14612.36,8406 r180 bottom
C32 "" C0402 14412.36,8290 r0 bottom
C33 "" C0402 14610.36,8292 r180 bottom
C34 "" C0402 14723.36,8289 r0 bottom
C35 "" C0402 14824.36,8151 r90 bottom
C36 "" C0402 14706.36,8117 r270 bottom
C37 "" C0402 14333.36,8290 r180 bottom
C38 "" C0402 14490.36,8171 r0 bottom
C39 "" C0402 14882.36,8289 r0 bottom
C40 "" C0402 14666.73,8191.23 r270 bottom
C41 "" C0402 14548.36,8116 r270 bottom
C42 "" C1210 14002.36,7576 r270 bottom
C43 "" C0603 14102.36,7566 r270 bottom
C44 "" C0402 14331.36,7699 r0 bottom
C45 "" C0402 14373.36,8015 r180 bottom
C46 "" C0402 14312.36,8152 r270 bottom
C47 "" C0402 14252.36,7779 r180 bottom
C48 "" C0402 14233.36,8276 r270 bottom
C49 "" C0402 14407.35,7932.42 r0 bottom
C50 "" C0402 14372.36,7857 r180 bottom
C51 "" C0402 14233.36,8111 r270 bottom
C52 "" C0402 14213.23,7620.88 r0 bottom
C53 "" C0402 14233.25,7957.37 r270 bottom
C54 "" C1210 14462.36,7326 r180 bottom
C55 "" C0603 14462.36,7426 r180 bottom
C56 "" C0402 14272.62,7561.96 r270 bottom
C57 "" C0402 14785.09,7639.57 r90 bottom
C58 "" C0402 14685.36,7739 r180 bottom
C59 "" C0402 14469.36,7681 r270 bottom
C60 "" C0402 14587.91,7561.37 r270 bottom
C61 "" C0402 14623.5,7639.89 r90 bottom
C62 "" C0402 14350.99,7600.26 r90 bottom
C63 "" C0402 14744.84,7560.29 r270 bottom
C64 "" C0402 14902.36,7563 r270 bottom
C65 "" C0402 14509.36,7717 r90 bottom
C66 "" C1210 15207.36,7621 r270 bottom
C67 "" C0603 15107.36,7626 r270 bottom
C68 "" C0402 14981.36,7799 r270 bottom
C69 "" C0402 14981.36,7915 r90 bottom
C70 "" C0402 14842.36,7858 r0 bottom
C71 "" C0402 15002.36,7620 r180 bottom
C72 "" C0402 14806.36,7936 r180 bottom
C73 "" C0402 14981.36,8073 r90 bottom
C74 "" C0402 15020.36,8312 r270 bottom
C75 "" C0402 14923.36,8172 r180 bottom
C76 "" C0402 14862.36,7993 r90 bottom
C77 "" C0402 14843.36,7699 r0 bottom
C78 "" C0402 13736.36,8618 r270 bottom
C79 "" C0402 13696.36,8618 r270 bottom
C80 "" C0402 13496.36,8618 r270 bottom
C81 "" C0402 13456.36,8618 r270 bottom
C82 "" C0402 13856.36,8618 r270 bottom
C83 "" C0402 13896.36,8618 r270 bottom
C84 "" C0402 13816.36,8618 r270 bottom
C85 "" C0402 13776.36,8618 r270 bottom
C86 "" C0402 13536.36,8618 r270 bottom
C87 "" C0402 13656.36,8618 r270 bottom
C88 "" C0402 13616.36,8618 r270 bottom
C89 "" C0402 13576.36,8618 r270 bottom
C90 "" C0402 15233.39,8619.07 r270 top
C91 "" C0402 15193.39,8619.07 r270 top
C92 "" C0402 15633.39,8619.07 r270 top
C93 "" C0402 15113.39,8619.07 r270 top
C94 "" C0402 15153.39,8619.07 r270 top
C95 "" C0402 15313.39,8619.07 r270 top
C96 "" C0402 15473.39,8619.07 r270 top
C97 "" C0402 15513.39,8619.07 r270 top
C98 "" C0402 15273.39,8619.07 r270 top
C99 "" C0402 15353.39,8619.07 r270 top
C100 "" C0402 15393.39,8619.07 r270 top
C101 "" C0402 15433.39,8619.07 r270 top
C102 "" C0402 13795.5,8200.03 r0 bottom
C103 "" C0402 14043.88,8027.56 r0 bottom
C104 "" C0402 15344.14,8219.48 r0 bottom
C105 "" C0402 15577.36,8106 r0 bottom
C106 "" C0402 13874.36,6402 r180 bottom
C107 "" C0402 13874.36,6438 r0 bottom
C108 "" C0402 14051.36,6265 r90 bottom
C109 "" C0402 14011.36,6265 r270 bottom
C110 "" C0402 14166.42,6261.54 r90 bottom
C111 "" C0402 14311.36,6245 r180 top
C112 "" C0402 14255.67,5543.68 r180 top
C113 "" C0402 14138.36,5551 r180 top
C114 "" C0402 14003.36,5546 r0 top
C115 "" C0402 14003.36,5376 r0 top
C116 "" C0402 14138.36,5376 r180 top
C117 "" C0402 14253.36,5376 r180 top
C118 "" C0603 13598.36,5507 r270 top
C119 "" C0402 16037.36,8631 r0 top
C120 "" C0402 15960.4,8599.95 r0 top
C121 "" C0402 15967.36,8496 r90 top
C122 "" C0402 15927.36,8496 r90 top
C123 "" C0402 15960.4,8559.95 r0 top
C124 "" C0402 16194.36,8456 r270 top
C125 "" C0402 16135.36,8631 r0 top
C128 "" C0805 15077.36,5976 r0 bottom
C129 "" C0402 15015.36,6562 r90 bottom
C132 "" C0402 15247.36,6176 r90 bottom
C133 "" C0402 15367.36,6176 r90 bottom
C135 "" C0402 15097.36,6046 r180 bottom
C136 "" C0402 15097.36,6086 r180 bottom
C141 "" C0402 15096.36,6247 r180 bottom
C142 "" C0402 15327.36,6176 r270 bottom
C143 "" C0402 15097.36,6464 r180 bottom
C144 "" C0402 15207.36,6176 r270 bottom
C145 "" C0402 15097.36,6126 r0 bottom
C146 "" C0402 15097.36,6166 r0 bottom
C147 "" C0603 14864.65,7336 r180 bottom
C148 "" C0603 14433.7,7194.05 r90 top
C149 "" C0603 14844.36,5574 r90 bottom
C150 "" C0402 15784.36,5204 r90 top
C153 "" CAP-SMD_BD5.0-L5.3-W5.3-FD 16087.36,10591 r270 top
C157 "" C0402 17170.36,9357 r90 bottom
C158 "" C0402 17505.55,9600.98 r270 bottom
C159 "" C0402 17476.36,9235 r270 bottom
C162 "" C0402 17047.36,9959 r90 bottom
C166 "" C0402 16968.36,9685 r180 bottom
C167 "" C0402 16968.36,9449 r180 bottom
C169 "" C0402 17365.36,9747 r90 bottom
C171 "" C0402 16992.36,9959 r270 bottom
C173 "" C0402 17507.36,9841 r0 bottom
C176 "" C0402 17235.36,9747 r90 bottom
C178 "" CAP-SMD_L3.5-W2.8-R-RD 17590.36,9549 r90 bottom
C179 "" CAP-SMD_L3.5-W2.8-R-RD 17567.36,9181 r90 bottom
C180 "" CAP-SMD_L3.5-W2.8-R-RD 17197.36,9969 r180 bottom
C181 "" CAP-SMD_L3.5-W2.8-R-RD 17567.36,9936 r180 bottom
C182 "" CAP-SMD_L3.5-W2.8-R-RD 14922.36,6616 r270 bottom
C183 "" CAP-SMD_L3.5-W2.8-R-RD 15532.36,6046 r180 bottom
C184 "" CAP-SMD_L3.5-W2.8-R-RD 15057.36,5866 r0 bottom
C185 "" C0402 16992.36,9357 r270 bottom
C186 "" C0402 17270.36,9357 r270 bottom
C187 "" C0402 17372.36,9429 r0 bottom
C188 "" C0402 17290.36,9747 r90 bottom
C189 "" C0402 17170.36,9747 r90 bottom
C190 "" C0402 17032.36,9748 r90 bottom
C191 "" C0402 15472.36,6141 r0 bottom
C192 "" CAP-SMD_BD5.0-L5.3-W5.3-FD 13564.36,10243 r270 top
C193 "" C0805 12959.36,9898 r0 top
C194 "" C0805 12803.36,9673 r180 top
C195 "" C0603 13083.36,9801 r90 top
C196 "" C0805 13780.36,9891 r0 top
C197 "" C0805 13632.31,9677.24 r180 top
C198 "" C0603 13908.36,9825 r90 top
C199 "" C0805 14596.31,9889.64 r180 top
C200 "" C0402 14455.38,9641.23 r0 top
C201 "" C0402 14366.99,9686.69 r0 top
C202 "" C0603 14712.81,9618.92 r270 bottom
C204 "" C1210 13496.26,8919.53 r90 top
C205 "" C1210 14000.18,8921.05 r90 top
C206 "" C1210 14775.51,9729.9 r270 top
C207 "" C1210 14978.23,9806.06 r270 top
C208 "" C1210 13496.5,8919.68 r90 bottom
C209 "" C1210 13994.92,8919.68 r90 bottom
C210 "" C0402 16272.36,9969 r0 top
C211 "" C1210 15883.94,6317.79 r0 top
C212 "" C1210 15881.65,5833 r0 top
C213 "" C1210 17528.83,10305.57 r90 top
C214 "" C1210 17951.36,10187 r270 top
C215 "" C1210 13493.36,6711 r0 bottom
C216 "" C1210 13493.36,6217 r0 bottom
C217 "" C0402 12965.36,9838 r180 top
C218 "" C0402 13785.36,9829 r180 top
C219 "" C0402 14595.47,9828.28 r0 top
C220 "" C0402 15593.39,8619.07 r270 top
C221 "" C0402 15553.39,8619.07 r270 top
C222 "" C0402 15113.74,8618.72 r270 bottom
C223 "" C0402 15153.74,8618.72 r270 bottom
C224 "" C0402 15193.74,8618.72 r270 bottom
C225 "" C0402 15233.74,8618.72 r270 bottom
C226 "" C0402 13655.41,8617.44 r270 top
C227 "" C0402 13616.36,8617.16 r270 top
C228 "" C0402 13576.36,8617.16 r270 top
C229 "" C0402 13536.36,8617.16 r270 top
C230 "" C0402 13496.36,8617.16 r270 top
C231 "" C0402 13456.36,8617.16 r270 top
C232 "" C0402 15633.74,8618.72 r270 bottom
C233 "" C0402 15593.74,8618.72 r270 bottom
C234 "" C0402 15553.74,8618.72 r270 bottom
C235 "" C0402 15513.74,8618.72 r270 bottom
C236 "" C0402 15473.74,8618.72 r270 bottom
C237 "" C0402 15433.74,8618.72 r270 bottom
C238 "" C0402 15313.74,8618.72 r270 bottom
C239 "" C0402 15273.74,8618.72 r270 bottom
C240 "" C0402 15393.74,8618.72 r270 bottom
C241 "" C0402 15353.74,8618.72 r270 bottom
C242 "" C0402 13816.92,8617.72 r270 top
C243 "" C0402 13774.74,8618 r270 top
C244 "" C0402 13734.79,8618 r270 top
C245 "" C0402 13694.85,8618 r270 top
C246 "" C0402 13936.36,8618 r270 bottom
C247 "" C0402 13976.36,8618 r270 bottom
C248 "" C0402 13975.74,8616.82 r270 top
C249 "" C0402 13935.74,8616.82 r270 top
C250 "" C0402 13895.74,8616.82 r270 top
C251 "" C0402 13855.74,8616.82 r270 top
C259 "" C1206 14051.36,8625 r90 top
C260 "" C1206 15716.05,8605.22 r90 top
C261 "" C0402 14018.84,8211.83 r90 bottom
C262 "" C0402 14023.62,7877.41 r90 bottom
C263 "" C0402 13930.8,7792.35 r0 bottom
C264 "" C0402 13947.51,8075.32 r180 bottom
C265 "" C0402 13652.36,7961 r0 bottom
C266 "" C0402 13677.36,8036 r90 bottom
C267 "" C0402 13677.36,8191 r90 bottom
C268 "" C0402 13677.36,8281 r270 bottom
C269 "" C0402 13820.98,8007.34 r90 bottom
C270 "" C0402 14024.57,7964.46 r90 bottom
C271 "" C0402 14022.36,7791 r90 bottom
C272 "" C0402 13883.14,7913.01 r90 bottom
C273 "" C0402 13725.36,7790 r0 bottom
C274 "" C0402 13677.36,7856 r90 bottom
C275 "" C0402 13652.36,7921 r0 bottom
C276 "" C0402 13826.1,8156.16 r180 bottom
C277 "" C0402 15211.73,8228.16 r90 bottom
C278 "" C0402 15210.25,8050.2 r90 bottom
C279 "" C0402 15187.36,7986 r0 bottom
C280 "" C0402 15254.58,7806.73 r0 bottom
C281 "" C0402 15187.95,8166.92 r0 bottom
C282 "" C0402 15430.45,8103.16 r270 bottom
C283 "" C0402 15408.61,8004.88 r270 bottom
C284 "" C0402 15553.47,8232.16 r90 bottom
C285 "" C0402 15212.36,8311 r270 bottom
C286 "" C0402 15350.75,8041.76 r270 bottom
C287 "" C0402 15187.36,7946 r0 bottom
C288 "" C0402 15212.36,7871 r90 bottom
C289 "" C0402 15444.36,7813 r0 bottom
C290 "" C0402 15551.82,7847.23 r270 bottom
C291 "" C0402 15552.36,7936 r270 bottom
C292 "" C0402 15552.36,8036 r270 bottom
C293 "" C0402 14547.82,7876.79 r270 bottom
C294 "" C0402 14546.62,7955.62 r270 bottom
C295 "" C0402 14667.36,7916 r270 bottom
C296 "" C0402 14666.9,7836.94 r270 bottom
C297 "" C0402 14707.36,7916 r90 bottom
C298 "" C0402 14627.36,7916 r90 bottom
C299 "" C0402 14587.36,7916 r270 bottom
C300 "" C0402 14667.36,7996 r270 bottom
C301 "" C0402 14587.36,7996 r270 bottom
C302 "" C0402 14508.36,7997 r270 bottom
C303 "" C0402 14508.36,8080 r270 bottom
C304 "" C0402 14547.73,7797.75 r270 bottom
C305 "" C0402 14468.36,7955 r270 bottom
C306 "" C0402 14469.28,7837.45 r90 bottom
C307 "" C0402 14725.36,8054 r0 bottom
C308 "" C0402 14746.91,7870.61 r90 bottom
C309 "" C0402 14391.36,7681 r270 bottom
C310 "" C0402 14430.36,7563 r270 bottom
C311 "" C0402 14389.36,8154 r270 bottom
C312 "" C1210 15874.7,7773.75 r180 bottom
C313 "" C1210 15876.67,8261.45 r180 bottom
C314 "" C0603 13082.69,6493.91 r90 top
C315 "" C0603 13138.36,6494 r90 top
C319 "" C0402 17338.04,7820.61 r270 bottom
C322 "" CAP-SMD_L3.2-W1.6-FD-1 17407.36,7796 r270 bottom
C328 "" C1210 17115.08,8619.65 r180 top
C329 "" C1210 17264.55,8319.64 r270 top
C330 "" C0402 17297.36,7821 r90 bottom
C331 "" C0402 17306.58,7704.15 r0 bottom
C332 "" C0402 17306.58,7744.15 r180 bottom
C333 "" C0402 17092.97,8075.17 r90 bottom
C334 "" C0402 17051.58,8074.15 r270 bottom
C335 "" C0402 16900.95,8018.05 r0 bottom
C336 "" C0402 16900.95,7978.05 r180 bottom
C337 "" C1210 16867.36,8416 r270 bottom
C338 "" C1210 17357.36,8416.28 r270 bottom
C339 "" C0402 16847.66,7872.98 r180 bottom
C340 "" C0402 16848.29,7832.98 r0 bottom
C341 "" C0402 17237.36,7776 r90 top
C342 "" C0402 17285.07,7795.88 r90 top
C343 "" C0402 16580.36,8378 r270 bottom
C344 "" C0402 16655.36,8494 r180 bottom
C345 "" C0603 16137.36,8176 r90 top
C346 "" C0603 16542.36,8176 r90 top
C347 "" C0603 16137.36,7521 r90 top
C348 "" C0603 16540.36,7503 r90 top
C349 "" C0603 16137.36,7836 r90 top
C350 "" C0603 16542.36,7826 r90 top
C351 "" C0805 15440.87,9888.21 r180 top
C352 "" C0805 15579.45,9572.47 r0 top
C353 "" C0805 15301.36,9707 r90 top
C354 "" C0805 17004.36,6498 r0 top
C355 "" C0805 17002.36,6073 r0 top
C356 "" C0805 17003.36,7043 r0 top
C357 "" C0805 17004.36,6612 r0 top
CN2 "" IDC-TH_10P-P2.54_C5665 12932.36,8966 r0 top
CN7 "" AUDIO-SMD_PJ-320D 17970,6921.77 r270 top
CN8 "" AUDIO-SMD_PJ-320D 17970,6360.5 r270 top
CN9 "" AUDIO-SMD_PJ-320D 17970,5921.18 r270 top
D1 "" SOT-23-3_L3.0-W1.7-P0.95-LS2.9-BR 12971.03,8582.33 r270 bottom
D2 "" SOT-23-3_L3.0-W1.7-P0.95-LS2.9-BR 12837.36,8582.33 r270 bottom
D3 "" SOT-23-3_L3.0-W1.7-P0.95-LS2.9-BR 13137.36,8582.33 r270 bottom
D4 "" SOT-23-3_L3.0-W1.7-P0.95-LS2.9-BR 12708.36,8583 r270 bottom
D5 "" SMA_L4.2-W2.6-LS5.3-RD 13286.75,5706.43 r180 top
D6 "" SOT-23-6_L2.9-W1.6-P0.95-LS2.7-BL 13824.73,5485.59 r90 top
D7 "" SLP2510P8_L2.5-W1.0-P0.50-BL 15292.25,5403.15 r90 top
D8 "" SLP2510P8_L2.5-W1.0-P0.50-BL 15292.1,5519.98 r90 top
D11 "" SMA_L4.2-W2.6-LS5.3-RD 14712.36,5397 r0 bottom
D12 "" SOT-23-6_L2.9-W1.6-P0.95-LS2.7-BL 15950.92,5586.33 r0 top
D13 "" SLP2510P8_L2.5-W1.0-P0.50-BL 17223.36,10685 r270 top
D14 "" SLP2510P8_L2.5-W1.0-P0.50-BL 17225.36,10558 r270 top
D16 "" SOT-23-6_L2.9-W1.6-P0.95-LS2.7-BL 16662.36,10326 r180 top
D17 "" SMA_L4.4-W2.6-LS5.0-RD 16352.36,10651 r0 top
D20 "" SOD-123F_L2.6-W1.6-LS3.5-RD 13092.36,10221 r270 top
D21 "" SOD-123F_L2.6-W1.6-LS3.5-RD 16714.64,10567.73 r90 top
D22 "" SOT-23-3_L3.0-W1.7-P0.95-LS2.9-BR 16637.19,10103.62 r90 top
D23 "" SOT-23-3_L3.0-W1.7-P0.95-LS2.9-BR 16147.31,5596.33 r180 top
D24 "" SOT-23-3_L3.0-W1.7-P0.95-LS2.9-BR 13628.36,5706 r180 top
D25 "" SOT-23-3_L3.0-W1.7-P0.95-LS2.9-BR 13887.77,5701.95 r180 top
D26 "" SOD-123FL_L2.8-W1.8-LS3.7-RD-1 12970.67,5895.23 r270 bottom
D29 "" SMA_L4.4-W2.6-LS5.0-RD 13266.36,5744 r90 bottom
D30 "" SOD-123F_L2.6-W1.6-LS3.5-RD 12865.67,5900.23 r270 bottom
D31 "" SOT-23-3_L3.0-W1.7-P0.95-LS2.9-BR 17507.36,7781 r270 top
D32 "" SOT-23-3_L3.0-W1.7-P0.95-LS2.9-BR 17507.36,7981 r90 top
D33 "" SOT-23-3_L3.0-W1.7-P0.95-LS2.9-BR 17507.36,8198 r90 top
D34 "" SOT-23-3_L3.0-W1.7-P0.95-LS2.9-BR 17254.36,7486 r180 bottom
DC3 "" DC-IN-TH_DC-091-A250 12847.36,10271 r0 top
DSUB1 "" DSUB-TH_DZ11A5X-H8R1-4F 13977.36,5196 r0 top
F1 "" F1812 16560,10577.49 r270 top
F2 "" F1812 13257.36,10326 r180 top
F3 "" F1812 13105.67,5900.23 r90 bottom
L1 "" L0805 16235.36,8597 r90 top
L2 "" L0603 14824.36,6569 r270 bottom
L3 "" L0603 15527.36,5951 r180 bottom
L4 "" L0603 15245.36,5866 r180 bottom
L5 "" L0603 17724.36,9624 r180 bottom
L6 "" L0603 17700.36,9256 r180 bottom
L7 "" L0603 17122.36,10094 r270 bottom
L8 "" L0603 17502.36,10071 r270 bottom
L22 "" IND-SMD_L7.0-W6.6 12882.36,9493 r180 top
L23 "" L0603 12647.36,9672 r180 top
L24 "" IND-SMD_L7.0-W6.6 13709.36,9485 r180 top
L25 "" L0603 13482.32,9676.29 r180 top
L26 "" IND-SMD_L7.0-W6.6 14729.91,9485 r0 top
L27 "" L0603 14876.62,9696.65 r90 top
L28 "" IND-SMD_L7.0-W6.6 13743.73,8979.85 r0 top
L29 "" IND-SMD_L7.0-W6.6 13744.01,8980.4 r0 bottom
L30 "" IND-SMD_L7.0-W6.6 15940.93,6073.77 r270 top
L31 "" IND-SMD_L7.0-W6.6 17739.86,10247.5 r270 top
L32 "" IND-SMD_L7.0-W6.6 13552.55,6469.19 r270 bottom
L33 "" L0603 13637.36,6189 r270 bottom
L34 "" IND-SMD_L7.0-W6.6 15816.65,8021.12 r90 bottom
L35 "" IND-SMD_4P-L2.0-W1.2-TL 12874.36,5975 r0 top
L36 "" L0603 12822.8,5740.16 r0 bottom
L37 "" L0603 17406.36,7957 r270 bottom
L38 "" L0603 17316.58,7649.15 r180 bottom
L39 "" IND-SMD_L7.0-W6.6 17054.06,8374.02 r270 top
L40 "" L0603 16841.58,7779.15 r0 bottom
L41 "" L0603 16908.36,8069 r180 bottom
L42 "" IND-SMD_L7.0-W6.6 17113.36,8357 r0 bottom
L44 "" L0603 15295.55,9887.91 r0 top
L45 "" L0603 15705.6,9602.02 r90 top
LED1 "" LED-ARRAY-SMD_4P-L1.9-W1.6-BL-CW 15297.36,7591 r180 top
Q1 "" SOT-23-3_L2.9-W1.3-P1.90-LS2.4-BR 13592.05,5896.04 r90 top
Q2 "" SOT-23-3_L2.9-W1.3-P1.90-LS2.4-BR 13446.36,5895.35 r90 top
Q3 "" SOT-23-3_L2.9-W1.3-P1.90-LS2.4-BR 13737.05,5896.04 r90 top
Q4 "" SOT-23-3_L2.9-W1.3-P1.90-LS2.4-BR 13882.05,5896.04 r90 top
Q5 "" SOT-23-3_L2.9-W1.3-P1.90-LS2.4-BR 16427.98,5651.71 r270 top
Q6 "" SOT-23-3_L2.9-W1.3-P1.90-LS2.4-BR 16582.98,5731.71 r270 top
Q7 "" SOT-23-3_L2.9-W1.3-P1.90-LS2.4-BR 16239.31,5375.41 r0 top
Q8 "" SOT-23-3_L2.9-W1.3-P1.90-LS2.4-BR 16239.31,5220.41 r0 top
Q9 "" SOT-23-3_L2.9-W1.3-P1.90-LS2.4-BR 16203.26,10067.36 r180 top
Q10 "" SOT-23-3_L2.9-W1.3-P1.90-LS2.4-BR 16353.26,10182.36 r270 top
Q11 "" SOT-23-3_L2.9-W1.3-P1.90-LS2.4-BR 16729.98,10005.31 r270 top
Q12 "" SOT-23-3_L2.9-W1.3-P1.90-LS2.4-BR 16537.19,9988.62 r270 top
Q13 "" SOT-23-3_L2.9-W1.3-P1.90-LS2.4-BR 14749.36,10346 r270 top
Q14 "" SOT-23-3_L2.9-W1.3-P1.90-LS2.4-BR 15039.36,10346 r270 top
Q15 "" SOT-23-3_L2.9-W1.3-P1.90-LS2.4-BR 15349.36,10346 r270 top
Q16 "" SOT-23-3_L2.9-W1.3-P1.90-LS2.4-BR 12712.36,7281 r90 bottom
Q17 "" SOT-23-3_L2.9-W1.3-P1.90-LS2.4-BR 17012.36,7414 r0 bottom
Q18 "" SOT-23-3_L2.9-W1.3-P1.90-LS2.4-BR 17015.36,7553 r0 bottom
R1 "" R0402 13656.32,8106.34 r180 bottom
R2 "" R0402 13967.36,8356 r0 bottom
R5 "" R0402 14279.71,7403.97 r270 bottom
R6 "" R0402 15003.36,7441 r90 bottom
R7 "" R0402 14963.36,7441 r90 bottom
R11 "" R0402 15042.36,7441 r90 bottom
R12 "" R0402 15827.36,7197 r0 top
R13 "" R0402 15312.36,7232 r180 top
R14 "" R0402 15827.36,7380 r0 top
R15 "" R0402 15827.36,7236 r0 top
R16 "" R0402 15312.36,7271 r180 top
R17 "" R0402 15827.36,7341 r0 top
R18 "" R0402 15202.36,7591 r90 top
R19 "" R0402 12971.03,8712.33 r270 bottom
R20 "" R0402 12837.36,8712.33 r270 bottom
R21 "" R0402 13137.36,8712.33 r270 bottom
R22 "" R0402 12707.36,8712.33 r270 bottom
R23 "" R0402 14142.36,7726 r90 bottom
R24 "" R0402 15262.36,7341 r180 top
R25 "" R0402 15327.36,7361 r270 top
R26 "" R0402 13610.54,8153.53 r180 bottom
R27 "" R0402 13706.36,8504 r90 top
R29 "" R0402 13946.36,8504 r90 bottom
R30 "" R0402 13746.36,8504 r90 top
R31 "" R0402 13192.69,6610.56 r90 top
R32 "" R0402 13746.36,8504 r90 bottom
R33 "" R0402 13666.36,8504 r90 top
R34 "" R0402 13946.36,8504 r90 top
R35 "" R0402 13786.36,8504 r90 top
R36 "" R0402 13906.36,8504 r90 bottom
R37 "" R0402 13786.36,8504 r90 bottom
R38 "" R0402 13706.36,8504 r90 bottom
R39 "" R0402 13546.36,8504 r90 bottom
R40 "" R0402 13826.36,8504 r90 bottom
R41 "" R0402 13826.36,8504 r90 top
R42 "" R0402 13626.36,8504 r90 top
R43 "" R0402 13546.36,8504 r90 top
R44 "" R0402 13906.36,8504 r90 top
R45 "" R0402 13866.36,8504 r90 top
R46 "" R0402 13626.36,8504 r90 bottom
R47 "" R0402 13586.36,8504 r90 bottom
R48 "" R0402 13866.36,8504 r90 bottom
R49 "" R0402 13666.36,8504 r90 bottom
R50 "" R0402 13586.36,8504 r90 top
R51 "" R0402 15190.67,8132.94 r180 bottom
R52 "" R0402 15492.36,8368 r0 bottom
R53 "" R0402 15148.7,8203.19 r180 bottom
R54 "" R0402 15318.12,8505.21 r90 bottom
R56 "" R0402 15557.71,8504.84 r90 bottom
R57 "" R0402 15358.02,8505.1 r90 top
R59 "" R0402 15358.12,8505.04 r90 bottom
R60 "" R0402 15318.12,8505.04 r90 top
R61 "" R0402 15437.94,8505.01 r90 bottom
R62 "" R0402 15397.56,8505.14 r90 bottom
R63 "" R0402 15437.94,8505.18 r90 top
R64 "" R0402 15397.86,8505.07 r90 top
R65 "" R0402 15277.86,8505.07 r90 top
R66 "" R0402 15278.02,8505.25 r90 bottom
R67 "" R0402 15477.76,8505.16 r90 bottom
R68 "" R0402 15477.7,8505.21 r90 top
R69 "" R0402 15237.99,8505.35 r90 bottom
R70 "" R0402 15197.78,8505.22 r90 bottom
R71 "" R0402 15517.76,8505.3 r90 bottom
R72 "" R0402 15517.54,8505.3 r90 top
R73 "" R0402 15237.95,8505.23 r90 top
R74 "" R0402 15158.49,8505.07 r90 bottom
R75 "" R0402 15558.66,8504.86 r90 top
R76 "" R0402 15197.89,8505.13 r90 top
R77 "" R0402 15158.43,8505.1 r90 top
R78 "" RES-ADJ-SMD_3224W 14327.36,5976 r0 top
R80 "" R0402 14306.36,6170 r0 bottom
R81 "" R0402 13948.36,6533 r270 bottom
R82 "" R0402 13908.36,6533 r270 bottom
R83 "" R0402 14246.63,6258.88 r90 bottom
R84 "" R0603 13936.36,6145 r0 top
R85 "" R0603 14056.36,6145 r0 top
R86 "" R0603 14176.36,6145 r180 top
R87 "" R0402 14306.36,6290 r0 top
R88 "" R0402 13592.05,5996.04 r0 top
R89 "" R0402 13447.05,5991.04 r0 top
R90 "" R0402 13509.52,5746.23 r180 top
R91 "" R0402 13509.52,5671.23 r0 top
R92 "" R0402 13737.05,5996.04 r0 top
R93 "" R0402 13882.05,5996.04 r0 top
R94 "" R0402 13770.36,5740 r180 top
R95 "" R0402 13864.38,5607.17 r180 top
R96 "" R0402 16032.36,8711 r180 top
R97 "" R0402 16036.36,8671 r180 top
R98 "" R0402 15104.36,6016 r0 top
R102 "" R0402 15574.36,6165 r270 top
R103 "" R0402 15614.36,6165 r90 top
R104 "" R0402 16344.31,5395.41 r270 top
R105 "" R0402 16344.31,5240.41 r270 top
R106 "" R0402 16086.36,5697 r180 top
R107 "" R0402 16087.31,5496.33 r0 top
R108 "" R0402 16747.19,9903.62 r180 top
R109 "" R0402 16552.19,9888.62 r180 top
R110 "" R0402 16727.19,10138.62 r90 top
R111 "" R0402 16537.36,10135 r270 top
R112 "" R0402 16337.36,10281 r180 top
R120 "" R0402 12685.19,6056.09 r90 bottom
R121 "" R0402 12683.16,5887.67 r270 bottom
R133 "" R0603 13210.36,9703 r90 top
R134 "" R0603 13138.36,9640 r90 top
R135 "" R0402 13080.36,9687 r90 top
R136 "" R0603 14027.33,9701 r90 top
R137 "" R0603 13961.44,9666.71 r90 top
R138 "" R0402 13906.07,9714.29 r90 top
R139 "" R0402 14707.32,9886.59 r270 top
R140 "" R0402 14455.74,9686.51 r0 top
R141 "" R0402 14449.3,9806.63 r0 top
R142 "" R0603 14436.63,9746.91 r180 top
R143 "" R0805 14563.18,10494.97 r270 top
R144 "" R0805 14844.36,10494.97 r270 top
R145 "" R0805 15147.36,10496 r270 top
R146 "" R0603 14978.59,9653.2 r180 top
R147 "" R0805 15435.36,10497 r270 top
R148 "" R0805 12832.36,7181 r90 bottom
R149 "" R0402 12707.36,7381 r180 bottom
R150 "" R0402 12617.36,8272 r180 bottom
R151 "" R0402 15228.36,6630 r90 bottom
R152 "" R0402 14684.65,7281 r90 bottom
R153 "" R0402 14520.59,7399.29 r0 top
R154 "" R0402 15482.36,7636 r0 top
R155 "" R0402 15356.13,8139.59 r90 bottom
R156 "" R0402 13844.8,8101.7 r90 bottom
R157 "" R0402 13272.69,6600.56 r0 top
R158 "" R0402 13252.69,6670.56 r270 top
R159 "" R0402 12847.69,6644.8 r180 top
R160 "" R0402 12847.69,6684.8 r180 top
R164 "" R0805 12646.1,6651 r180 bottom
R165 "" R0805 12642.36,6756 r180 bottom
R168 "" R0402 12617.36,7926 r180 bottom
R169 "" R0402 12617.36,7602 r180 bottom
R170 "" R0402 17208.36,8018 r180 top
R171 "" R0402 16927.04,7631.79 r180 top
R172 "" R0402 16927.04,7676.79 r180 top
R173 "" R0402 17285.36,7713 r90 top
R174 "" R0805 17387.36,8193 r90 top
R175 "" R0805 17387.36,7991 r270 top
R176 "" R0805 17387.36,7776 r90 top
R177 "" R0402 17132.36,7661 r90 top
R180 "" R0402 16912.36,7419 r90 bottom
R181 "" R0402 16912.36,7550 r90 bottom
R182 "" R0402 17138.36,7414 r180 bottom
R183 "" R0402 17137.36,7552 r0 bottom
R184 "" R0402 14612.36,7411 r90 bottom
R185 "" R0402 15337.36,7701 r270 top
R186 "" R0402 15351.36,7963 r270 bottom
R187 "" R0402 15409.36,7926.68 r270 bottom
R188 "" R0402 13822.36,7922 r270 bottom
R189 "" R0402 13881.36,7993 r90 bottom
R190 "" R0402 14508.36,8349 r270 bottom
R191 "" R0402 17838.36,6690 r0 top
R192 "" R0402 17838.36,6650 r0 top
R193 "" R1206 17868.36,7185 r0 top
R194 "" R1206 18073.36,6677 r0 top
R195 "" R0402 15697.85,9719.23 r90 top
R196 "" R0402 13097.36,8254 r90 bottom
R197 "" R0402 13098.36,7909 r90 bottom
R198 "" R0402 13097.36,7584 r90 bottom
RN1 "" RES-ARRAY-SMD_0402-8P-L2.0-W1.0-BL 14782.36,6981 r0 top
RN2 "" RES-ARRAY-SMD_0603-8P-L3.2-W1.6-BL 14740.36,5909 r0 top
RN3 "" RES-ARRAY-SMD_0603-8P-L3.2-W1.6-BL 16200.57,9563 r270 top
RN4 "" RES-ARRAY-SMD_0402-8P-L2.0-W1.0-BL 15177.36,6981 r0 top
RN5 "" RES-ARRAY-SMD_0402-8P-L2.0-W1.0-BL 15401.36,6981 r0 top
RN6 "" RES-ARRAY-SMD_0402-8P-L2.0-W1.0-BL 15496.36,6981 r0 top
RN7 "" RES-ARRAY-SMD_0402-8P-L2.0-W1.0-BL 14237.36,8831 r180 top
RN8 "" RES-ARRAY-SMD_0402-8P-L2.0-W1.0-BL 14337.36,8831 r180 top
RN9 "" RES-ARRAY-SMD_0402-8P-L2.0-W1.0-BL 14432.36,8831 r180 top
RN11 "" RES-ARRAY-SMD_0402-8P-L2.0-W1.0-BL 14627.36,8831 r180 top
RN12 "" RES-ARRAY-SMD_0402-8P-L2.0-W1.0-BL 14722.36,8831 r180 top
RN13 "" RES-ARRAY-SMD_0402-8P-L2.0-W1.0-BL 14817.36,8831 r180 top
RN14 "" RES-ARRAY-SMD_0402-8P-L2.0-W1.0-BL 14482.36,6981 r0 top
RN15 "" RES-ARRAY-SMD_0402-8P-L2.0-W1.0-BL 14382.36,6981 r0 top
RN16 "" RES-ARRAY-SMD_0402-8P-L2.0-W1.0-BL 13882.36,6981 r0 top
RN17 "" RES-ARRAY-SMD_0402-8P-L2.0-W1.0-BL 13982.36,6981 r0 top
RN18 "" RES-ARRAY-SMD_0402-8P-L2.0-W1.0-BL 14082.36,6981 r0 top
RN19 "" RES-ARRAY-SMD_0402-8P-L2.0-W1.0-BL 14182.36,6981 r0 top
RN20 "" RES-ARRAY-SMD_0402-8P-L2.0-W1.0-BL 14282.36,6981 r0 top
RN21 "" RES-ARRAY-SMD_0402-8P-L2.0-W1.0-BL 14917.36,8831 r180 top
RN22 "" RES-ARRAY-SMD_0402-8P-L2.0-W1.0-BL 14681.36,6981 r0 top
RN23 "" RES-ARRAY-SMD_0402-8P-L2.0-W1.0-BL 15081.36,6981 r0 top
RN24 "" RES-ARRAY-SMD_0402-8P-L2.0-W1.0-BL 14582.36,6981 r0 top
RN25 "" RES-ARRAY-SMD_0402-8P-L2.0-W1.0-BL 14882.36,6981 r0 top
RN27 "" RES-ARRAY-SMD_0402-8P-L2.0-W1.0-BL 14981.36,6981 r0 top
RN28 "" RES-ARRAY-SMD_0402-8P-L2.0-W1.0-BL 14528.9,8831.69 r180 top
SW1 "" SW-SMD_8P-L6.7-W5.4-P1.27-LS8.4 14739.36,6169 r0 top
SW2 "" SW-SMD_8P-L6.7-W5.4-P1.27-LS8.4 16459.36,9557 r270 top
SW3 "" KEY-SMD_2P-L6.0-W6.0-P6.00 12852.36,8271 r0 top
SW4 "" KEY-SMD_2P-L6.0-W6.0-P6.00 12852.36,7926 r0 top
SW5 "" KEY-SMD_2P-L6.0-W6.0-P6.00 12847.36,7601 r0 top
TP19 "" Test-Point-0.5mm 12864.7,6601.85 r90 top
TP20 "" Test-Point-0.5mm 12864.07,6726.85 r90 top
U2 "" HTQFP-100_L14.0-W14.0-P0.50-LS16.0-BL-EP6.2 17170.36,9547 r270 top locked
U3 "" HTQFP-64_L10.0-W10.0-P0.50-LS12.0-BL-EP5.0 15237.36,6316 r270 top locked
U4 "" LFCSP-48_L7.0-W7.0-P0.50-BL-EP5.1 14051.36,6330 r180 top locked
U5 "" FBGA-96_L14.0-W8.0-R16-C6-P0.80-TL 13852.36,8076 r180 top locked
U7 "" WSON-10_L3.0-W3.0-P0.50-BL-EP 16092.36,8516 r270 top
U8 "" FBGA-484_L23.0-W23.0-R22-C22-P1.00-TL 14607.36,7916 r0 top locked
U11 "" TEST-RING 13509.72,10796 r0 top
U12 "" FBGA-96_L14.0-W8.0-R16-C6-P0.80-TL 15382.36,8096 r180 top locked
U13 "" SOT-23-3_L2.9-W1.6-P1.90-LS2.8-BR 14336.36,6155 r180 top
U14 "" R0402 13834.95,6195.97 r90 top
U15 "" L0603 14230.67,5458.68 r270 top
U16 "" L0603 14113.36,5461 r270 top
U17 "" L0603 14023.36,5461 r270 top
U18 "" F1812 13446.36,5476 r0 top
U19 "" SOIC-8_L4.9-W3.9-P1.27-LS6.0-BL 15969.31,5300.41 r90 top
U21 "" R0603 14832.36,6176 r0 bottom
U22 "" L0603 14864.65,7411 r180 bottom
U23 "" L0603 14363.7,7194.05 r90 top
U24 "" F1812 14684.36,5606 r0 bottom
U25 "" R0603 16427.98,5536.71 r180 top
U26 "" R0603 16577.98,5611.71 r0 top
U27 "" R0603 16612.98,5836.71 r0 top
U31 "" R0603 16353.26,10067.36 r0 top
U33 "" SOIC-8_L5.0-W4.0-P1.27-LS6.0-BL 16272.36,9836 r270 top
U69 "" TQFN-16_L3.0-W3.0-P0.50-TL-EP1.7 12968.29,9725.73 r90 top
U70 "" TQFN-16_L3.0-W3.0-P0.50-TL-EP1.7 13796.01,9721.48 r90 top
U71 "" VQFN-14_L3.5-W3.5-P0.50-TL-EP_TPS54622RHLT 14594.47,9714.86 r270 top
U72 "" TEST-RING 13712.76,10796 r0 top
U73 "" TEST-RING 13915.8,10796 r0 top
U74 "" TEST-RING 14118.84,10796 r0 top
U75 "" TEST-RING 13306.67,10796 r0 top
U76 "" TEST-RING 17221.41,5204.18 r0 top
U77 "" LED1206-RD 14563.18,10720.67 r270 top
U78 "" LED1206-RD 14844.36,10720.48 r270 top
U79 "" LED1206-RD 15144.36,10716 r270 top
U80 "" LED1206-RD 15434.36,10716 r270 top
U81 "" LED1206-RD 12657.36,7156 r0 top
U82 "" SMD_SMTSO3060CTJ 18137.05,5236 r180 bottom
U83 "" SMD_SMTSO3060CTJ 12722.05,5266 r180 bottom
U84 "" SMD_SMTSO3060CTJ 18137.05,10701 r180 bottom
U85 "" SMD_SMTSO3060CTJ 12722.05,10701 r180 bottom
U86 "" MARK 13002.36,5231 r180 bottom
U87 "" MARK 12997.36,10706 r180 bottom
U88 "" MARK 13002.36,5231 r0 top
U89 "" MARK 12997.49,10706 r0 top
U90 "" MARK 17862.36,10706 r180 bottom
U91 "" MARK 17862.36,10706 r0 top
U92 "" MARK 17862.36,5231 r180 bottom
U93 "" MARK 17862.36,5231 r0 top
U94 "" MARK 15102.36,8416 r0 top
U95 "" MARK 15607.36,8421 r0 top
U96 "" MARK 14062.36,8401 r0 top
U97 "" MARK 14107.36,7416 r0 top
U98 "" MARK 15177.36,7771 r0 top
U99 "" MARK 13647.36,7746 r0 top
U100 "" SC-70-5_L2.0-W1.3-P0.65-LS2.1-BL 15427.36,7536 r0 top
U101 "" R0603 14882.98,6424.06 r180 bottom
U102 "" R0603 14882.98,6346.36 r180 bottom
U104 "" QFN-28_L5.0-W5.0-P0.50-TL-EP3.3 13022.69,6668.91 r90 top
U105 "" R0402 13192.69,6695.56 r90 top
U106 "" SOIC-14_L8.7-W3.9-P1.27-LS6.0-BL 17042.36,6287 r180 top
U108 "" LED1206-RD 12642.36,6651 r0 top
U109 "" LED1206-RD 12642.36,6761 r0 top
U111 "" LFCSP-40_L6.0-W6.0-P0.50-BL-EP4.1 17063.66,7849.27 r270 top locked
U112 "" C0402 17272.36,7921 r0 bottom
U114 "" SOT-23-5_L2.9-W1.6-P0.95-LS2.8-BR 16674.22,8399.24 r90 bottom
U115 "" TSSOP-24_L7.8-W4.4-P0.65-LS6.4-BL 16337.36,8011 r270 top locked
U116 "" TSSOP-24_L7.8-W4.4-P0.65-LS6.4-BL 16337.36,7681 r270 top locked
U117 "" TSSOP-24_L7.8-W4.4-P0.65-LS6.4-BL 16337.36,7351 r270 top locked
U118 "" RCA-Y 18245.44,8408.1 r90 top locked
U120 "" MINI_DIN_4 18129.08,7829.41 r270 top locked
U121 "" R0603 14832.36,6301 r180 bottom
U122 "" R0603 14832.36,6236 r0 bottom
U123 "" SOIC-8_L5.3-W5.3-P1.27-LS8.0-BL 15556.18,7316.26 r90 top
U124 "" SOIC-14_L8.7-W3.9-P1.27-LS6.0-BL 17042.36,6816 r180 top
U125 "" SOIC-8_L4.9-W3.9-P1.27-LS6.0-BL 15510.36,9721 r270 top
U126 "" TEST-RING 14309.36,10796 r0 top
USB2 "" HDMI-SMD_HDMI-001C 15062.54,5399.71 r270 top
USB3 "" HDMI-SMD_HDMI-001C 16952.36,10511 r90 top
USB4 "" USB-C-SMD_TYPE-C-6PIN-2MD-073 12685.01,5973.23 r270 top
X1 "" OSC-SMD_4P-L3.2-W2.5-BL 14795.33,7228.98 r180 bottom
X2 "" OSC-SMD_4P-L3.2-W2.5-BL 14538.7,7264.05 r90 top

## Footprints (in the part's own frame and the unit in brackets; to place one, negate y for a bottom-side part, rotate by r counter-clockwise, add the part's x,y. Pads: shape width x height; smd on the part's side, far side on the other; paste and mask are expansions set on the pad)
AUDIO-SMD_PJ-320D [mm]
  rect 3x1.4 smd: 1(-3,-4.05) 2(3,4.05) 3(3,1.05) 4(3,-2.95)
  Board Outline Layer circle w0.003: c0,-1.45 r0.6
  Board Outline Layer circle w0.003: c0,5.55 r0.6
  Board Outline Layer region: 0,-0.85 0.26,-0.91 0.469,-1.076 0.585,-1.317 0.585,-1.584 0.469,-1.824 0.26,-1.991 0,-2.05 0,-2.05 -0.26,-1.991 -0.469,-1.824 -0.585,-1.584 -0.585,-1.317 -0.469,-1.076 -0.26,-0.91 0,-0.85
  Board Outline Layer region: 0,-0.85 0.26,-0.91 0.469,-1.076 0.585,-1.317 0.585,-1.584 0.469,-1.824 0.26,-1.991 0,-2.05 0,-2.05 -0.26,-1.991 -0.469,-1.824 -0.585,-1.584 -0.585,-1.317 -0.469,-1.076 -0.26,-0.91 0,-0.85
  Board Outline Layer region: 0,6.15 0.26,6.09 0.469,5.924 0.585,5.683 0.585,5.416 0.469,5.176 0.26,5.009 0,4.95 0,4.95 -0.26,5.009 -0.469,5.176 -0.585,5.416 -0.585,5.683 -0.469,5.924 -0.26,6.09 0,6.15
  Board Outline Layer region: 0,6.15 0.26,6.09 0.469,5.924 0.585,5.683 0.585,5.416 0.469,5.176 0.26,5.009 0,4.95 0,4.95 -0.26,5.009 -0.469,5.176 -0.585,5.416 -0.585,5.683 -0.469,5.924 -0.26,6.09 0,6.15
  silkscreen extent -3.12,-4.98 3.13,9.37
C0402 [mm]
  rect 0.68x0.54 smd: 1(-0.545,0) 2(0.545,0)
  silkscreen extent -1.05,-0.45 1.05,0.45
C0603 [mm]
  rect 0.8x0.9 smd: 1(-0.7,0) 2(0.7,0)
  silkscreen extent -1.41,-0.71 1.39,0.72
C0805 [mm]
  rect 1.41x1.35 smd: 1(-1,0) 2(1,0)
  silkscreen extent -1.96,-0.9 1.96,0.9
C1206 [mm]
  rect 1.485x1.728 smd: 1(-1.593,0) 2(1.593,0)
  silkscreen extent -2.56,-1.09 2.56,1.09
C1210 [mm]
  rect 1.635x2.7 smd: 1(-1.517,0) 2(1.517,0)
  silkscreen extent -2.56,-1.58 2.56,1.58
CAP-SMD_BD5.0-L5.3-W5.3-FD [mm]
  rect 2.8x1.1 smd: 1(-2.1,0) 2(2.1,0)
  silkscreen extent -2.66,-2.62 2.66,2.65
CAP-SMD_L3.2-W1.6-FD-1 [mm]
  rect 1.2x1.5 smd: 1(-1.2,0) 2(1.2,0)
  silkscreen extent -2.41,-1.02 2.03,1.02
CAP-SMD_L3.5-W2.8-R-RD [mm]
  rect 1.9x2.376 smd: 1(1.899,0) 2(-1.899,0)
  silkscreen extent -1.83,-1.55 2.21,1.55
DC-IN-TH_DC-091-A250 [mm]
  round 2.5 hole 1.5: 3(3.325,0)
  oval 1.6x3 hole 0.914 slot 2 at 90 deg: 4(-2.925,0)
  oval 3.2x1.6 hole 0.914 slot 2.4 at 0 deg: 6(-3.325,4.725) 6(1.275,-4.725) 6(1.275,4.725)
  oval 3.2x1.6 hole 0.914 slot 2.4 at 0 deg copper offset 0,0: 6(-3.325,-4.725)
  Board Outline Layer circle w0.003: c-6.325,0 r0.8
  Board Outline Layer region: -5.525,0 -5.604,-0.347 -5.826,-0.625 -6.147,-0.78 -6.503,-0.78 -6.824,-0.625 -7.046,-0.347 -7.125,0 -7.125,0 -7.046,0.347 -6.824,0.625 -6.503,0.78 -6.147,0.78 -5.826,0.625 -5.604,0.347 -5.525,0
  Board Outline Layer region: -5.525,0 -5.604,-0.347 -5.826,-0.625 -6.147,-0.78 -6.503,-0.78 -6.824,-0.625 -7.046,-0.347 -7.125,0 -7.125,0 -7.046,0.347 -6.824,0.625 -6.503,0.78 -6.147,0.78 -5.826,0.625 -5.604,0.347 -5.525,0
  silkscreen extent -9.07,-5.08 3.99,5
DSUB-TH_DZ11A5X-H8R1-4F [mm]
  round 1.3 hole 0.9: 1(3.812,0.75) 2(1.524,-0.75) 3(-0.763,0.75) 4(-3.051,-0.75) 5(-5.338,0.75) 6(5.337,0.75) 7(3.049,-0.75) 8(0.762,0.75) 9(-1.526,-0.75) 10(-3.813,0.75) 11(4.574,-0.75) 12(2.287,0.75) 13(-0.001,-0.75) 14(-2.288,0.75) 15(-4.576,-0.75)
  oval 4.2x1.5 hole 0.8 slot 3.2 at 0 deg: 16(-12.5,0.5) 17(12.5,0.5)
  Board Outline Layer circle w0.003: c-8,1.2 r0.8
  Board Outline Layer circle w0.003: c8,1.2 r0.8
  Board Outline Layer region: -7.2,1.2 -7.279,0.853 -7.501,0.575 -7.822,0.42 -8.178,0.42 -8.499,0.575 -8.721,0.853 -8.8,1.2 -8.8,1.2 -8.721,1.547 -8.499,1.826 -8.178,1.98 -7.822,1.98 -7.501,1.826 -7.279,1.547 -7.2,1.2
  Board Outline Layer region: -7.2,1.2 -7.279,0.853 -7.501,0.575 -7.822,0.42 -8.178,0.42 -8.499,0.575 -8.721,0.853 -8.8,1.2 -8.8,1.2 -8.721,1.547 -8.499,1.826 -8.178,1.98 -7.822,1.98 -7.501,1.826 -7.279,1.547 -7.2,1.2
  Board Outline Layer region: 8.8,1.2 8.721,0.853 8.499,0.575 8.178,0.42 7.822,0.42 7.501,0.575 7.279,0.853 7.2,1.2 7.2,1.2 7.279,1.547 7.501,1.826 7.822,1.98 8.178,1.98 8.499,1.826 8.721,1.547 8.8,1.2
  Board Outline Layer region: 8.8,1.2 8.721,0.853 8.499,0.575 8.178,0.42 7.822,0.42 7.501,0.575 7.279,0.853 7.2,1.2 7.2,1.2 7.279,1.547 7.501,1.826 7.822,1.98 8.178,1.98 8.499,1.826 8.721,1.547 8.8,1.2
  silkscreen extent -16,-8.8 16,2.05
F1812 [mil]
  rect 55.38x137.76 smd: 1(-72.97,0) 2(72.97,0)
  silkscreen extent -110,-80 110,80
FBGA-96_L14.0-W8.0-R16-C6-P0.80-TL [mm]
  round 0.394 smd: A1(-3.2,6) A2(-2.4,6) A3(-1.6,6) A7(1.6,6) A8(2.4,6) A9(3.2,6) B1(-3.2,5.2) B2(-2.4,5.2) B3(-1.6,5.2) B7(1.6,5.2) B8(2.4,5.2) B9(3.2,5.2) C1(-3.2,4.4) C2(-2.4,4.4) C3(-1.6,4.4) C7(1.6,4.4) C8(2.4,4.4) C9(3.2,4.4) D1(-3.2,3.6) D2(-2.4,3.6) D3(-1.6,3.6) D7(1.6,3.6) D8(2.4,3.6) D9(3.2,3.6) E1(-3.2,2.8) E2(-2.4,2.8) E3(-1.6,2.8) E7(1.6,2.8) E8(2.4,2.8) E9(3.2,2.8) F1(-3.2,2) F2(-2.4,2) F3(-1.6,2) F7(1.6,2) F8(2.4,2) F9(3.2,2) G1(-3.2,1.2) G2(-2.4,1.2) G3(-1.6,1.2) G7(1.6,1.2) G8(2.4,1.2) G9(3.2,1.2) H1(-3.2,0.4) H2(-2.4,0.4) H3(-1.6,0.4) H7(1.6,0.4) H8(2.4,0.4) H9(3.2,0.4) J1(-3.2,-0.4) J2(-2.4,-0.4) J3(-1.6,-0.4) J7(1.6,-0.4) J8(2.4,-0.4) J9(3.2,-0.4) K1(-3.2,-1.2) K2(-2.4,-1.2) K3(-1.6,-1.2) K7(1.6,-1.2) K8(2.4,-1.2) K9(3.2,-1.2) L1(-3.2,-2) L2(-2.4,-2) L3(-1.6,-2) L7(1.6,-2) L8(2.4,-2) L9(3.2,-2) M1(-3.2,-2.8) M2(-2.4,-2.8) M3(-1.6,-2.8) M7(1.6,-2.8) M8(2.4,-2.8) M9(3.2,-2.8) N1(-3.2,-3.6) N2(-2.4,-3.6) N3(-1.6,-3.6) N7(1.6,-3.6) N8(2.4,-3.6) N9(3.2,-3.6) P1(-3.2,-4.4) P2(-2.4,-4.4) P3(-1.6,-4.4) P7(1.6,-4.4) P8(2.4,-4.4) P9(3.2,-4.4) R1(-3.2,-5.2) R2(-2.4,-5.2) R3(-1.6,-5.2) R7(1.6,-5.2) R8(2.4,-5.2) R9(3.2,-5.2) T1(-3.2,-6) T2(-2.4,-6) T3(-1.6,-6) T7(1.6,-6) T8(2.4,-6) T9(3.2,-6)
  silkscreen extent -4.55,-7.08 4.08,7.3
